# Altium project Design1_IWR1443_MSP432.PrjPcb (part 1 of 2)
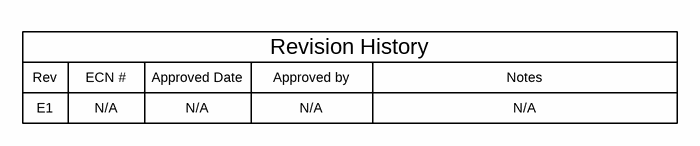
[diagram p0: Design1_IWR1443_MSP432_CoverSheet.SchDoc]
CopyrightYear: 2016; PCB_Layout: N/A; PCB_Rev: E1; PRJ_Customer: Public Release; PRJ_Engineer: Michelle Liu; PRJ_Title: Design1 with IR1443 and MSP432; SCH_Rev: E1; TechSupport: http://www.ti.com/support; TID: N/A
6 sheets, 236 parts. Net scope: global (net labels, ports and power ports of the same name join across sheets).
Sheets:
  Design1_IWR1443_MSP432_CoverSheet.SchDoc
  Design1_IWR1443_interfaces.SchDoc
  Design1_MSP432.SchDoc
  Design1_LowVoltage.SchDoc
  Design1_HighVoltage.SchDoc
  Design1_EVM_Hardware.SchDoc

## Sheet Design1_IWR1443_MSP432_CoverSheet.SchDoc: Block Diagram
size 431 x 279 mm; Date: Not shown in title block; ApprovedBy: Not shown in title block; CheckedBy: Not shown in title block; Author: Not shown in title block; CompanyName: Not shown in title block; DrawnBy: Michelle Liu; Engineer: Not shown in title block; Organization: Not shown in title block; Address1: Not shown in title block; Address2: Not shown in title block; Address3: Not shown in title block; Address4: Not shown in title block; DocumentNumber: 1; Revision: Use project parameter SCH_Rev; SheetNumber: 1; SheetTotal: 6; PageSetup: Record=PageOptions¦CenterHorizontal=True¦CenterVertical=True¦PrintScale=1.00¦XCorrection=1.00¦YCorrection=1.00¦PrintKind=0¦BorderSize=5000000¦LeftOffset=0¦BottomOffset=0¦Orientation=2¦PaperLength=1000¦PaperWidth=1000¦Scale=100¦PaperSource=15¦PrintQuality=600¦MediaType=1¦DitherType=10¦PaperKind=Letter¦PrintScaleMode=1

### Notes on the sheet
- Rev
- E1
- ECN #
- N/A
- Approved Date
- Approved by
- Revision History
- Notes

## Sheet Design1_IWR1443_interfaces.SchDoc: IWR1443
size 431 x 279 mm; Date: Not shown in title block; ApprovedBy: Not shown in title block; CheckedBy: Not shown in title block; Author: Not shown in title block; CompanyName: Not shown in title block; DrawnBy: Michelle Liu; Engineer: Not shown in title block; Organization: Not shown in title block; Address1: Not shown in title block; Address2: Not shown in title block; Address3: Not shown in title block; Address4: Not shown in title block; DocumentNumber: 2; Revision: Use project parameter SCH_Rev; SheetNumber: 2; SheetTotal: 6; PageSetup: Record=PageOptions¦CenterHorizontal=True¦CenterVertical=True¦PrintScale=1.00¦XCorrection=1.00¦YCorrection=1.00¦PrintKind=0¦BorderSize=5000000¦LeftOffset=0¦BottomOffset=0¦Orientation=2¦PaperLength=1000¦PaperWidth=1000¦Scale=100¦PaperSource=15¦PrintQuality=-3¦MediaType=1¦DitherType=10¦PrintScaleMode=1¦PaperKind=Letter¦PaperIndex=1
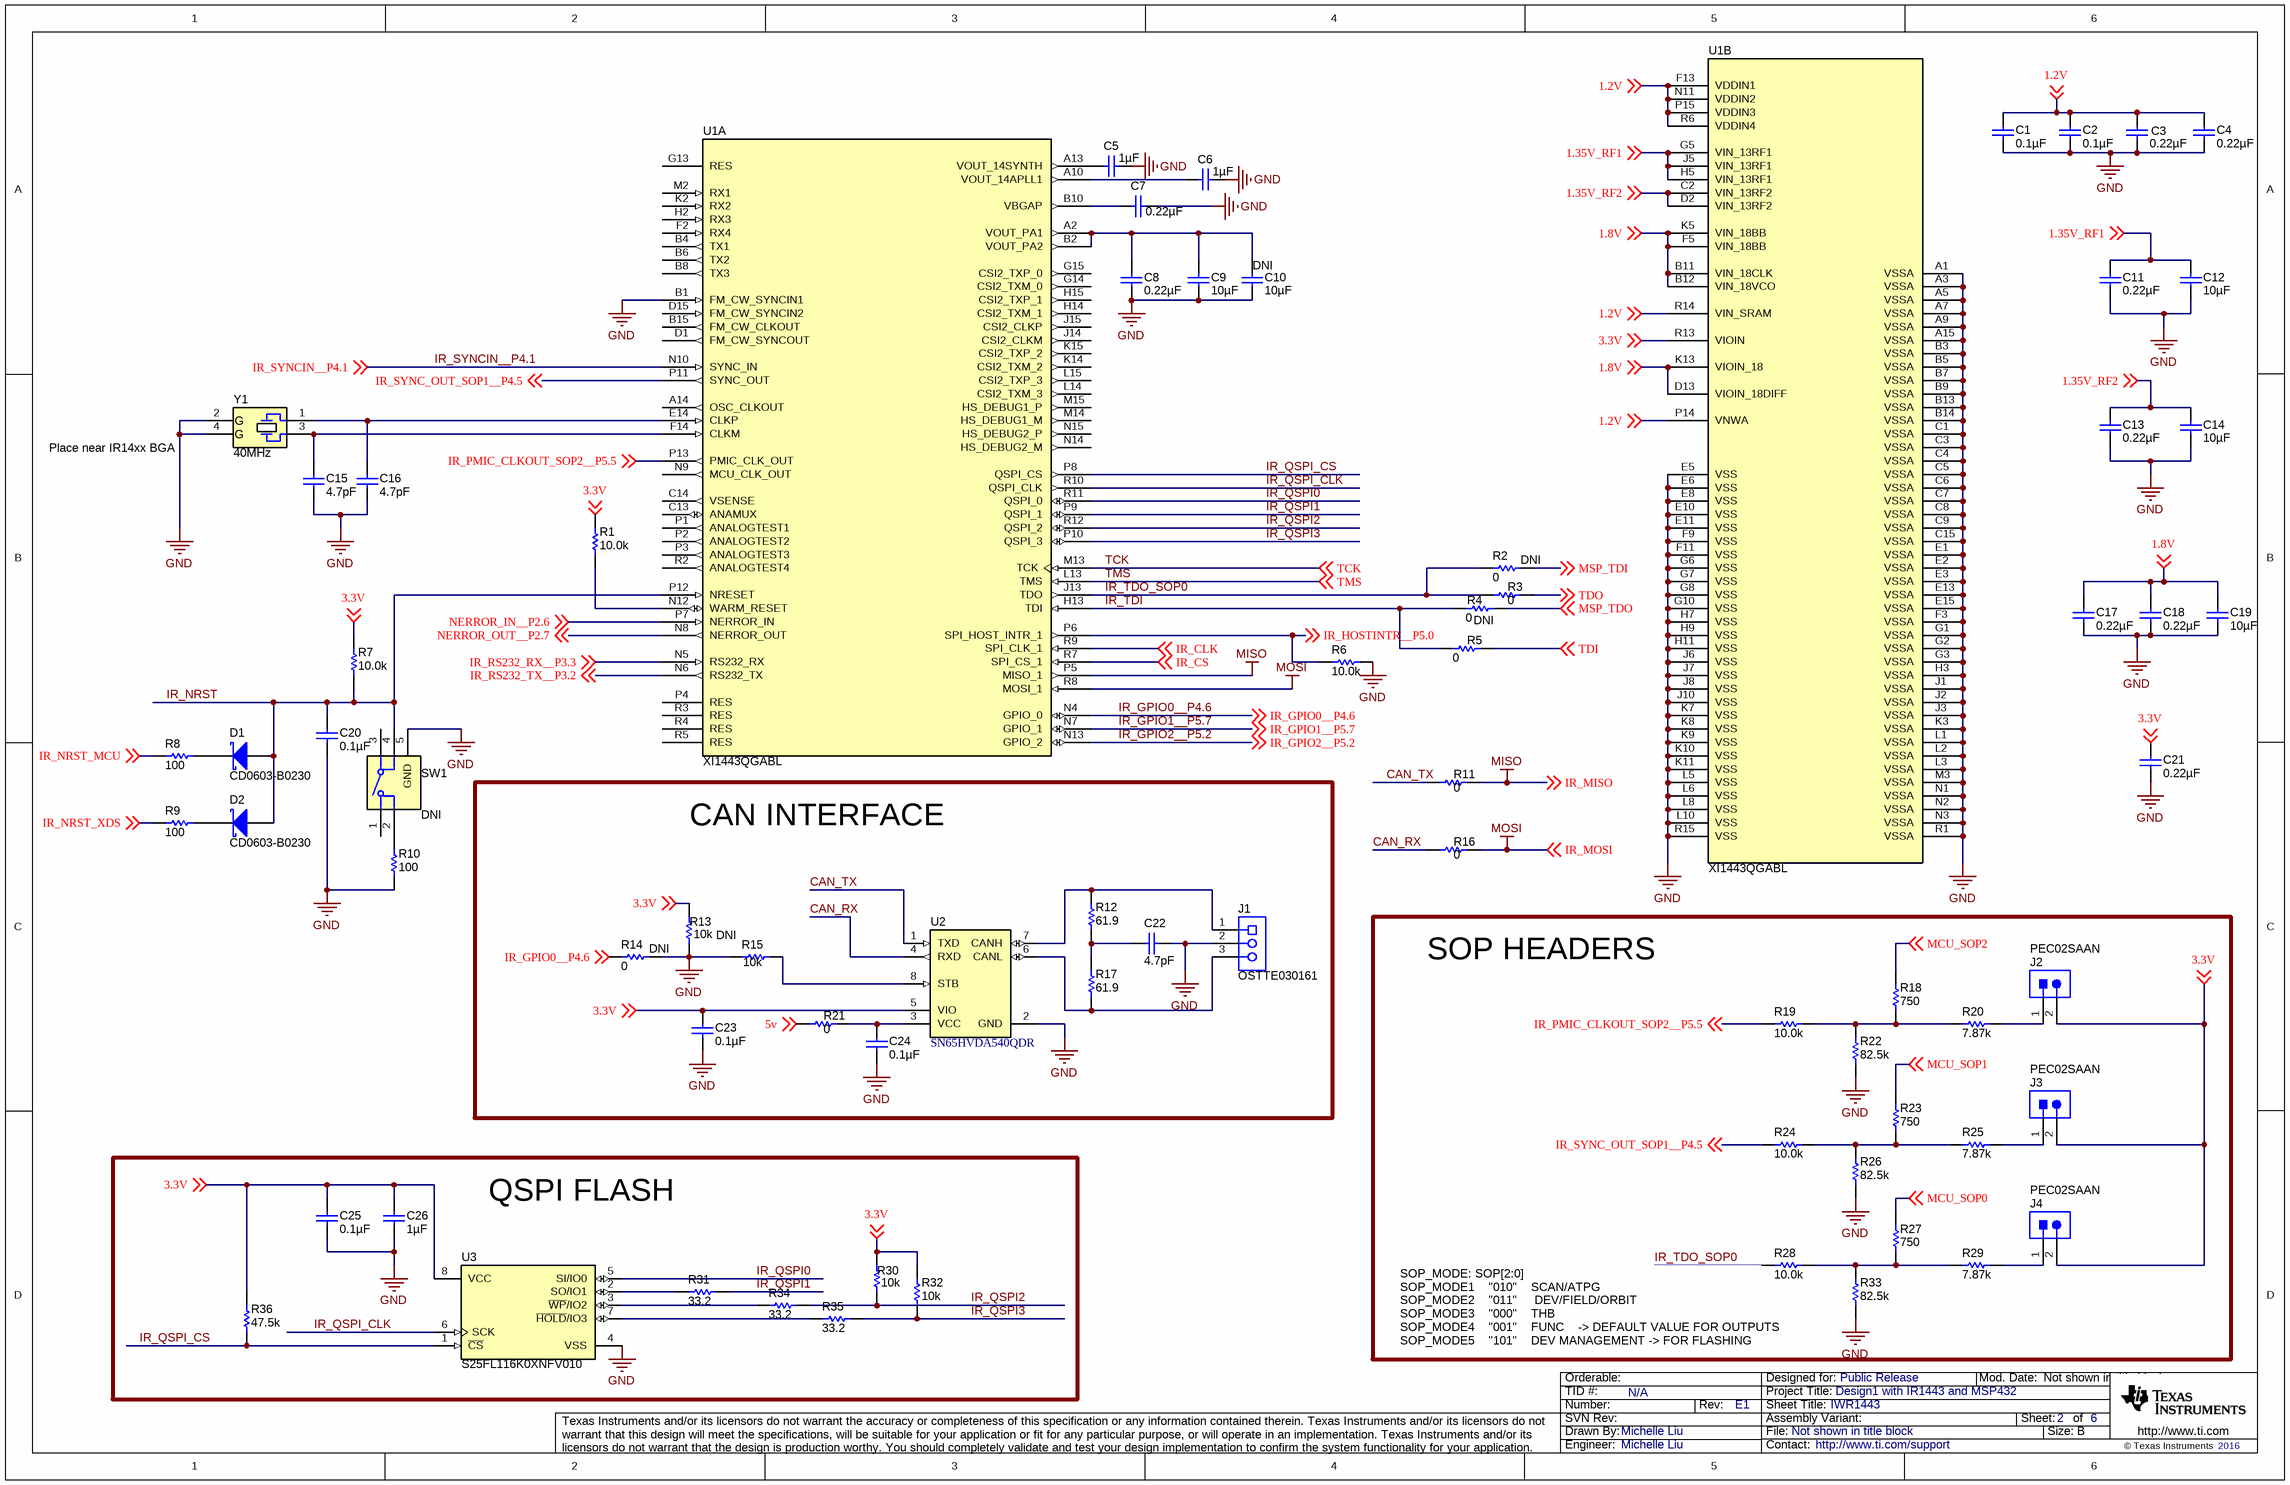
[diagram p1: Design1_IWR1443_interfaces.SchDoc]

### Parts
C1  ValueDisplayed: 0.1µF  [0402]  (hidden comment: GCM155R71C104KA55D)
C2  ValueDisplayed: 0.1µF  [0402]  (hidden comment: GCM155R71C104KA55D)
C3  ValueDisplayed: 0.22µF  [0603]  (hidden comment: GCM155R71C224KE02)
C4  ValueDisplayed: 0.22µF  [0603]  (hidden comment: GCM155R71C224KE02)
C5  ValueDisplayed: 1µF  [0603]  (hidden comment: GCM188R71C105KA64D)
C6  ValueDisplayed: 1µF  [0603]  (hidden comment: GCM188R71C105KA64D)
C7  ValueDisplayed: 0.22µF  [0603]  (hidden comment: GCM155R71C224KE02)
C8  ValueDisplayed: 0.22µF  [0603]  (hidden comment: GCM155R71C224KE02)
C9  ValueDisplayed: 10µF  [0805_HV]  (hidden comment: GCM21BR71A106KE22L)
C10  DNI  ValueDisplayed: 10µF  [0805_HV]
C11  ValueDisplayed: 0.22µF  [0603]  (hidden comment: GCM155R71C224KE02)
C12  ValueDisplayed: 10µF  [0805_HV]  (hidden comment: GCM21BR71A106KE22L)
C13  ValueDisplayed: 0.22µF  [0603]  (hidden comment: GCM155R71C224KE02)
C14  ValueDisplayed: 10µF  [0805_HV]  (hidden comment: GCM21BR71A106KE22L)
C15  ValueDisplayed: 4.7pF  [0402]  (hidden comment: GRM1555C1H4R7WA01D)
C16  ValueDisplayed: 4.7pF  [0402]  (hidden comment: GRM1555C1H4R7WA01D)
C17  ValueDisplayed: 0.22µF  [0603]  (hidden comment: GCM155R71C224KE02)
C18  ValueDisplayed: 0.22µF  [0603]  (hidden comment: GCM155R71C224KE02)
C19  ValueDisplayed: 10µF  [0805_HV]  (hidden comment: GCM21BR71A106KE22L)
C20  ValueDisplayed: 0.1µF  [0402]  (hidden comment: GCM155R71C104KA55D)
C21  ValueDisplayed: 0.22µF  [0603]  (hidden comment: GCM155R71C224KE02)
C22  ValueDisplayed: 4.7pF  [0402]  (hidden comment: GJM1555C1H4R7BB01D)
C23  ValueDisplayed: 0.1µF  [0402]  (hidden comment: CGA2B3X7R1H104K050BB)
C24  ValueDisplayed: 0.1µF  [0402]  (hidden comment: CGA2B3X7R1H104K050BB)
C25  ValueDisplayed: 0.1µF  [0402]  (hidden comment: C1005X5R1A104K050BA)
C26  ValueDisplayed: 1µF  [0402S]  (hidden comment: GRM155R6YA105ME11D)
D1  CD0603-B0230  [Diode_0603]
D2  CD0603-B0230  [Diode_0603]
J1  OSTTE030161  [On-Shore_OSTTE030161]
J2  PEC02SAAN  [CONN_PEC02SAAN]
J3  PEC02SAAN  [CONN_PEC02SAAN]
J4  PEC02SAAN  [CONN_PEC02SAAN]
R1  ValueDisplayed: 10.0k  [0402]  (hidden comment: CRCW040210K0FKED)
R2  DNI  ValueDisplayed: 0  [0402]
R3  ValueDisplayed: 0  [0402]  (hidden comment: RC0402JR-070RL)
R4  DNI  ValueDisplayed: 0  [0402]
R5  ValueDisplayed: 0  [0402]  (hidden comment: RC0402JR-070RL)
R6  ValueDisplayed: 10.0k  [0402]  (hidden comment: CRCW040210K0FKED)
R7  ValueDisplayed: 10.0k  [0402]  (hidden comment: CRCW040210K0FKED)
R8  ValueDisplayed: 100  [0402]  (hidden comment: ERJ-2GEJ101X)
R9  ValueDisplayed: 100  [0402]  (hidden comment: ERJ-2GEJ101X)
R10  ValueDisplayed: 100  [0402]  (hidden comment: ERJ-2GEJ101X)
R11  ValueDisplayed: 0  [0402]  (hidden comment: RC0402JR-070RL)
R12  ValueDisplayed: 61.9  [0402]  (hidden comment: CRCW040261R9FKED)
R13  DNI  ValueDisplayed: 10k  [0402]
R14  DNI  ValueDisplayed: 0  [0402]
R15  ValueDisplayed: 10k  [0402]  (hidden comment: CRCW040210K0JNED)
R16  ValueDisplayed: 0  [0402]  (hidden comment: RC0402JR-070RL)
R17  ValueDisplayed: 61.9  [0402]  (hidden comment: CRCW040261R9FKED)
R18  ValueDisplayed: 750  [0402]  (hidden comment: CRCW0402750RFKED)
R19  ValueDisplayed: 10.0k  [0402]  (hidden comment: CRCW040210K0FKED)
R20  ValueDisplayed: 7.87k  [0402]  (hidden comment: CRCW04027K87FKED)
R21  ValueDisplayed: 0  [0402]  (hidden comment: RC0402JR-070RL)
R22  ValueDisplayed: 82.5k  [0402]  (hidden comment: CRCW040282K5FKED)
R23  ValueDisplayed: 750  [0402]  (hidden comment: CRCW0402750RFKED)
R24  ValueDisplayed: 10.0k  [0402]  (hidden comment: CRCW040210K0FKED)
R25  ValueDisplayed: 7.87k  [0402]  (hidden comment: CRCW04027K87FKED)
R26  ValueDisplayed: 82.5k  [0402]  (hidden comment: CRCW040282K5FKED)
R27  ValueDisplayed: 750  [0402]  (hidden comment: CRCW0402750RFKED)
R28  ValueDisplayed: 10.0k  [0402]  (hidden comment: CRCW040210K0FKED)
R29  ValueDisplayed: 7.87k  [0402]  (hidden comment: CRCW04027K87FKED)
R30  ValueDisplayed: 10k  [0402]  (hidden comment: CRCW040210K0JNED)
R31  ValueDisplayed: 33.2  [0201]  (hidden comment: CRCW020133R2FNED)
R32  ValueDisplayed: 10k  [0402]  (hidden comment: CRCW040210K0JNED)
R33  ValueDisplayed: 82.5k  [0402]  (hidden comment: CRCW040282K5FKED)
R34  ValueDisplayed: 33.2  [0201]  (hidden comment: CRCW020133R2FNED)
R35  ValueDisplayed: 33.2  [0201]  (hidden comment: CRCW020133R2FNED)
R36  ValueDisplayed: 47.5k  [0402]  (hidden comment: CRCW040247K5FKED)
SW1  DNI  [SW_KMR243GLFG]
U1  XI1443QGABL  [ABL0161A]  (parts A,B of 2)
U2  SN65HVDA540QDR  [D0008A_N]
U3  S25FL116K0XNFV010  [WND008]
Y1  Frequency: 40MHz  [Kyocera_CX3225SA]  (hidden comment: CX3225SA40000D0PTWCC)

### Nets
1.2V: C1.1 C2.1 C3.1 C4.1 U1.F13(VDDIN1) U1.N11(VDDIN2) U1.P14(VNWA) U1.P15(VDDIN3) U1.R6(VDDIN4) U1.R14(VIN_SRAM) ; off-sheet 1.2V
1.8V: C17.1 C18.1 C19.1 U1.B11(VIN_18CLK) U1.B12(VIN_18VCO) U1.D13(VIOIN_18DIFF) U1.F5(VIN_18BB) U1.K5(VIN_18BB) U1.K13(VIOIN_18) ; off-sheet 1.8V
1.35V_RF1: C11.1 C12.1 U1.G5(VIN_13RF1) U1.H5(VIN_13RF1) U1.J5(VIN_13RF1) ; off-sheet 1.35V_RF1
1.35V_RF2: C13.1 C14.1 U1.C2(VIN_13RF2) U1.D2(VIN_13RF2) ; off-sheet 1.35V_RF2
3.3V: C21.1 C23.1 C25.1 C26.1 J2.2 J3.2 J4.2 R1.2 R7.2 R13.2 R30.2 R32.2 R36.2 U1.R13(VIOIN) U2.5(VIO) U3.8(VCC) ; off-sheet 3.3V
5v: R21.1 ; off-sheet 5v
GND: C1.2 C2.2 C3.2 C4.2 C5.1 C6.1 C7.1 C8.2 C9.2 C10.2 C11.2 C12.2 C13.2 C14.2 C15.2 C16.2 C17.2 C18.2 C19.2 C20.2 C21.2 C22.1 C23.2 C24.2 C25.2 C26.2 J1.2 R6.1 R10.1 R13.1 R14.2 R15.2 R22.1 R26.1 R33.1 SW1.5(GND) U1.A1(VSSA) U1.A3(VSSA) U1.A5(VSSA) U1.A7(VSSA) U1.A9(VSSA) U1.A15(VSSA) U1.B1(FM_CW_SYNCIN1) U1.B3(VSSA) U1.B5(VSSA) U1.B7(VSSA) U1.B9(VSSA) U1.B13(VSSA) U1.B14(VSSA) U1.C1(VSSA) U1.C3(VSSA) U1.C4(VSSA) U1.C5(VSSA) U1.C6(VSSA) U1.C7(VSSA) U1.C8(VSSA) U1.C9(VSSA) U1.C15(VSSA) U1.E1(VSSA) U1.E2(VSSA) U1.E3(VSSA) U1.E5(VSS) U1.E6(VSS) U1.E8(VSS) U1.E10(VSS) U1.E11(VSS) U1.E13(VSSA) U1.E15(VSSA) U1.F3(VSSA) U1.F9(VSS) U1.F11(VSS) U1.G1(VSSA) U1.G2(VSSA) U1.G3(VSSA) U1.G6(VSS) U1.G7(VSS) U1.G8(VSS) U1.G10(VSS) U1.H3(VSSA) U1.H7(VSS) U1.H9(VSS) U1.H11(VSS) U1.J1(VSSA) U1.J2(VSSA) U1.J3(VSSA) U1.J6(VSS) U1.J7(VSS) U1.J8(VSS) U1.J10(VSS) U1.K3(VSSA) U1.K7(VSS) U1.K8(VSS) U1.K9(VSS) U1.K10(VSS) U1.K11(VSS) U1.L1(VSSA) U1.L2(VSSA) U1.L3(VSSA) U1.L5(VSS) U1.L6(VSS) U1.L8(VSS) U1.L10(VSS) U1.M3(VSSA) U1.N1(VSSA) U1.N2(VSSA) U1.N3(VSSA) U1.R1(VSSA) U1.R15(VSS) U2.2(GND) U3.4(VSS) Y1.2(GND) Y1.4(GND)
MISO: R11.2 U1.P5(MISO_1) ; off-sheet IR_MISO  [also labelled IR_MISO]
MOSI: R16.2 U1.R8(MOSI_1) ; off-sheet IR_MOSI  [also labelled IR_MOSI]
CAN_RX: R16.1 U2.4(RXD)
CAN_TX: R11.1 U2.1(TXD)
IR_CLK: U1.R9(SPI_CLK_1) ; off-sheet IR_CLK
IR_CS: U1.R7(SPI_CS_1) ; off-sheet IR_CS
IR_GPIO0__P4.6: R14.1 U1.N4(GPIO_0) ; off-sheet IR_GPIO0__P4.6
IR_GPIO1__P5.7: U1.N7(GPIO_1) ; off-sheet IR_GPIO1__P5.7
IR_GPIO2__P5.2: U1.N13(GPIO_2) ; off-sheet IR_GPIO2__P5.2
IR_HOSTINTR__P5.0: R6.2 U1.P6(SPI_HOST_INTR_1) ; off-sheet IR_HOSTINTR__P5.0
IR_NRST: C20.1 D1.2(A) D2.2(A) R7.1 SW1.4 U1.P12(NRESET)
IR_NRST_MCU: R8.1 ; off-sheet IR_NRST_MCU
IR_NRST_XDS: R9.1 ; off-sheet IR_NRST_XDS
IR_PMIC_CLKOUT_SOP2__P5.5: R19.2 U1.P13(PMIC_CLK_OUT) ; off-sheet IR_PMIC_CLKOUT_SOP2__P5.5
IR_QSPI0: U1.R11(QSPI_0) U3.5(SI/IO0)
IR_QSPI1: R31.2 U1.P9(QSPI_1)
IR_QSPI2: R30.1 R34.2 U1.R12(QSPI_2)
IR_QSPI3: R32.1 R35.2 U1.P10(QSPI_3)
IR_QSPI_CLK: U1.R10(QSPI_CLK) U3.6(SCK)
IR_QSPI_CS: R36.1 U1.P8(QSPI_CS) U3.1(~{CS})
IR_RS232_RX__P3.3: U1.N5(RS232_RX) ; off-sheet IR_RS232_RX__P3.3
IR_RS232_TX__P3.2: U1.N6(RS232_TX) ; off-sheet IR_RS232_TX__P3.2
IR_SYNC_OUT_SOP1__P4.5: R24.2 U1.P11(SYNC_OUT) ; off-sheet IR_SYNC_OUT_SOP1__P4.5
IR_SYNCIN__P4.1: U1.N10(SYNC_IN) ; off-sheet IR_SYNCIN__P4.1
IR_TDI: R4.1 R5.1 U1.H13(TDI)
IR_TDO_SOP0: R2.1 R3.1 R28.2 U1.J13(TDO)
MCU_SOP0: R27.2 ; off-sheet MCU_SOP0
MCU_SOP1: R23.2 ; off-sheet MCU_SOP1
MCU_SOP2: R18.2 ; off-sheet MCU_SOP2
MSP_TDI: R2.2 ; off-sheet MSP_TDI
MSP_TDO: R4.2 ; off-sheet MSP_TDO
NERROR_IN__P2.6: U1.P7(NERROR_IN) ; off-sheet NERROR_IN__P2.6
NERROR_OUT__P2.7: U1.N8(NERROR_OUT) ; off-sheet NERROR_OUT__P2.7
TCK: U1.M13(TCK) ; off-sheet TCK
TDI: R5.2 ; off-sheet TDI
TDO: R3.2 ; off-sheet TDO
TMS: U1.L13(TMS) ; off-sheet TMS
NetC5_2: C5.2 U1.A13(VOUT_14SYNTH)
NetC6_2: C6.2 U1.A10(VOUT_14APLL1)
NetC7_2: C7.2 U1.B10(VBGAP)
NetC8_1: C8.1 C9.1 C10.1 U1.A2(VOUT_PA1) U1.B2(VOUT_PA2)
NetC15_1: C15.1 U1.F14(CLKM) Y1.3
NetC16_1: C16.1 U1.E14(CLKP) Y1.1
NetC22_2: C22.2 R12.1 R17.2
NetC24_1: C24.1 R21.2 U2.3(VCC)
NetD1_1: D1.1(K) R8.2
NetD2_1: D2.1(K) R9.2
NetJ1_1: J1.1 R12.2 U2.7(CANH)
NetJ1_3: J1.3 R17.1 U2.6(CANL)
NetJ2_1: J2.1 R20.2
NetJ3_1: J3.1 R25.2
NetJ4_1: J4.1 R29.2
NetR1_1: R1.1 U1.N12(WARM_RESET)
NetR10_2: R10.2 SW1.2
NetR15_1: R15.1 U2.8(STB)
NetR18_1: R18.1 R19.1 R20.1 R22.2
NetR23_1: R23.1 R24.1 R25.1 R26.2
NetR27_1: R27.1 R28.1 R29.1 R33.2
NetR31_1: R31.1 U3.2(SO/IO1)
NetR34_1: R34.1 U3.3(~{WP}/IO2)
NetR35_1: R35.1 U3.7(~{HOLD}/IO3)

Not connected (* = marked no-connect by the designer): SW1 1 3; U1 A14(OSC_CLKOUT) B4(TX1) B6(TX2) B8(TX3) B15(FM_CW_CLKOUT) C13(ANAMUX) C14(VSENSE) D1(FM_CW_SYNCOUT) D15(FM_CW_SYNCIN2) F2(RX4) G13(RES) G14(CSI2_TXM_0) G15(CSI2_TXP_0) H2(RX3) H14(CSI2_TXM_1) H15(CSI2_TXP_1) J14(CSI2_CLKM) J15(CSI2_CLKP) K2(RX2) K14(CSI2_TXM_2) K15(CSI2_TXP_2) L14(CSI2_TXM_3) L15(CSI2_TXP_3) M2(RX1) M14(HS_DEBUG1_M) M15(HS_DEBUG1_P) N9(MCU_CLK_OUT) N14(HS_DEBUG2_M) N15(HS_DEBUG2_P) P1(ANALOGTEST1) P2(ANALOGTEST2) P3(ANALOGTEST3) P4(RES) R2(ANALOGTEST4) R3(RES) R4(RES) R5(RES)

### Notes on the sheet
- IWR1443
- Place near IR14xx BGA
- CAN INTERFACE
- SOP HEADERS
- QSPI FLASH
- (near R28) SOP_MODE: SOP[2:0]
  SOP_MODE1    "010"    SCAN/ATPG
  SOP_MODE2    "011"     DEV/FIELD/ORBIT
  SOP_MODE3    "000"    THB
  SOP_MODE4    "001"    FUNC    -> DEFAULT VALUE FOR OUTPUTS
  SOP_MODE5    "101"    DEV MANAGEMENT -> FOR FLASHING

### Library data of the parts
C1 C2 C20 = GCM155R71C104KA55D: CAP, CERM, 0.1 µF, 16 V, +/- 10%, X7R, 0402; Manufacturer: MuRata; Polarized: N; CompType: Capacitor; Value: 0.1uF; U/M: EA; Cap_F: 0.0000001; Tolerance_%: 10; Value1: Unknown; VDC_V: 16; Value2: 16V; TaMin_C: -55; TaMax_C: 125; SizeArea_mm2: 0.5; SizeAreaWB_mm2: 3; SizeX_mm: 1; SizeZ_mm: 0.6; AEC Category: Q200
C3 C4 C7 C8 C11 C13 C17 C18 C21 = GCM155R71C224KE02: CAP, CERM, 0.22 µF, 16 V, +/- 10%, X7R, AEC-Q200 Grade 1, 0603; Manufacturer: MuRata; Polarized: N; CompType: Capacitor; Value: 0.22uF; U/M: EA; Cap_F: 0.00000022; Tolerance_%: 10; Value1: Unknown; VDC_V: 16; Value2: 16V; TaMin_C: -55; TaMax_C: 125; SizeArea_mm2: 1.28; SizeAreaWB_mm2: 4.68; SizeX_mm: 1.6; SizeY_mm: 0.8; SizeZ_mm: 1; AEC Category: Q200; AEC Qualified: Y
C5 C6 = GCM188R71C105KA64D: CAP, CERM, 1 µF, 16 V, +/- 10%, X7R, AEC-Q200 Grade 1, 0603; Manufacturer: MuRata; Polarized: N; CompType: Capacitor; Value: 1uF; U/M: EA; Cap_F: 0.000001; Tolerance_%: 10; Value1: Unknown; VDC_V: 16; Value2: 16V; TaMin_C: -55; TaMax_C: 125; SizeArea_mm2: 1.28; SizeAreaWB_mm2: 4.68; SizeX_mm: 1.6; SizeY_mm: 0.8; SizeZ_mm: 1; AEC Category: Q200; AEC Qualified: Y
C9 C10 C12 C14 C19 = GCM21BR71A106KE22L: CAP, CERM, 10 µF, 10 V, +/- 10%, X7R, 0805; Manufacturer: MuRata; Polarized: N; CompType: Capacitor; Value: 10uF; U/M: EA; Cap_F: 0.00001; Tolerance_%: 10; Value1: Unknown; Value2: 10V; TaMin_C: -55; TaMax_C: 125; Cap_Case: 0805; SizeArea_mm2: 2.5; SizeAreaWB_mm2: 6.75; SizeX_mm: 2; SizeY_mm: 1.25; SizeZ_mm: 1.45; AEC Category: Q200
C15 C16 = GRM1555C1H4R7WA01D: CAP, CERM, 4.7 pF, 50 V, +/- 1%, C0G/NP0, 0402; Manufacturer: MuRata; Polarized: N; CompType: Capacitor; Value: 4.7pF; U/M: EA; Cap_F: 0.0000000000047; Tolerance_%: 1; Value1: Unknown; VDC_V: 50; Value2: 50V; TaMin_C: -55; TaMax_C: 125; SizeArea_mm2: 0.5; SizeAreaWB_mm2: 3; SizeZ_mm: 0.6; AEC Category: Q200
C22 = GJM1555C1H4R7BB01D: CAP, CERM, 4.7 pF, 50 V, +/- 2%, C0G/NP0, 0402; Manufacturer: MuRata; Polarized: N; CompType: Capacitor; Value: 4.7pF; U/M: EA; Cap_F: 0.0000000000047; Tolerance_%: 2; Value1: Unknown; VDC_V: 50; Value2: 50V; TaMin_C: -55; TaMax_C: 125; SizeArea_mm2: 0.5; SizeAreaWB_mm2: 3; SizeX_mm: 1; SizeZ_mm: 0.6; AEC Category: Q200
C23 C24 = CGA2B3X7R1H104K050BB: CAP, CERM, 0.1 µF, 50 V, +/- 10%, X7R, AEC-Q200 Grade 1, 0402; Manufacturer: TDK; Polarized: N; CompType: Capacitor; Value: 0.1uF; U/M: EA; Cap_F: 0.0000001; Tolerance_%: 10; ESR_ohm: 0.039064; Value1: 0.039064 ohm; VDC_V: 50; Value2: 50V; IRMS_A: 0.814669; TaMin_C: -55; TaMax_C: 125; SizeArea_mm2: 0.5; SizeAreaWB_mm2: 3; SizeX_mm: 1; SizeZ_mm: 0.6; AEC Category: Q200; AEC Qualified: Y
C25 = C1005X5R1A104K050BA: CAP, CERM, 0.1 µF, 10 V, +/- 10%, X5R, 0402; Manufacturer: TDK; Polarized: N; CompType: Capacitor; Value: 0.1uF; U/M: EA; Cap_F: 0.0000001; Tolerance_%: 10; Value1: Unknown; Value2: 10V; TaMin_C: -55; TaMax_C: 85; SizeArea_mm2: 0.5; SizeAreaWB_mm2: 3; SizeX_mm: 1; SizeZ_mm: 0.6; AEC Category: Q200
C26 = GRM155R6YA105ME11D: CAP, CERM, 1 µF, 35 V, +/- 20%, X5R, 0402; Manufacturer: MuRata; Polarized: N; CompType: Capacitor; Value: 1uF; U/M: EA; Cap_F: 0.000001; Tolerance_%: 20; Value1: Unknown; VDC_V: 35; Value2: 35V; TaMin_C: -55; TaMax_C: 85; Cap_Case: 0402; SizeArea_mm2: 0.5; SizeAreaWB_mm2: 3; SizeX_mm: 1; SizeZ_mm: 0.6; AEC Category: Q200
D1 D2 = CD0603-B0230: Diode, Schottky, 35 V, 0.2 A, 0603 Diode; Manufacturer: Bourns; U/M: EA; Vf_V: 0.5; Value: 35V; Value1: 0.2A; Value2: 0.5V; Io_A: 0.2; Vr_V: 35; TJmax_C: 125; SizeAreaWB_mm2: 5.13; SizeArea_mm2: 1.53; SizeX_mm: 1.7; SizeY_mm: 0.9; SizeZ_mm: 0.75; AEC Category: Q101
J1 = OSTTE030161: Terminal Block, 3.5mm, 3x1, Tin, R/A, TH; Manufacturer: On-Shore Technology; SymbolCreator: a0412235; Pitch_mm: 3.5; Gender: Female; Row_Count: 1; Current_A: 10; Voltage_V: 125; Cert_CSA: Y
J2-J4 = PEC02SAAN: Header, 100mil, 2x1, Tin, TH; Manufacturer: Sullins Connector Solutions; SymbolCreator: a0412235; Pitch_mm: 2.54; Gender: Male; Shrouded: N; Row_Count: 1; Current_A: 3; Voltage_V: 1800; Cert_UL: Y
R1 R6 R7 R19 R24 R28 = CRCW040210K0FKED: RES, 10.0 k, 1%, 0.063 W, 0402; Manufacturer: Vishay-Dale; CompType: Resistor; Value: 10.0k; Res_ohm: 10000; Value_Code: 10k0; Tolerance_%: 1; Power_W: 0.063; Value2: 0.063W; VDC_V: 50; TempCo: 100 ppm/C; SizeArea_mm2: 0.5; SizeZ_mm: 0.6; EIA_Code: E96; U/M: EA; AEC Category: Q200
R2-R5 R11 R14 R16 R21 = RC0402JR-070RL: RES, 0, 5%, 0.063 W, 0402; Manufacturer: Yageo America; CompType: Resistor; Value: 0; Value_Code: 0000; Tolerance_%: 5; Power_W: 0.063; Value2: 0.063W; VDC_V: 50; TempCo: 200 ppm/C; SizeArea_mm2: 0.5; SizeX_mm: 1; SizeZ_mm: 0.6; EIA_Code: E24; U/M: EA; AEC Category: Q200
R8-R10 = ERJ-2GEJ101X: RES, 100, 5%, 0.1 W, AEC-Q200 Grade 0, 0402; Manufacturer: Panasonic; CompType: Resistor; Value: 100; Value_Code: 100R; Tolerance_%: 5; Power_W: 0.1; Value2: 0.1W; TempCo: 200 ppm/C; SizeArea_mm2: 0.5; SizeX_mm: 1; SizeZ_mm: 0.6; EIA_Code: E24; U/M: EA; AEC Category: Q200; AEC Qualified: Y; AEC Grade: 0
R12 R17 = CRCW040261R9FKED: RES, 61.9, 1%, 0.063 W, 0402; Manufacturer: Vishay-Dale; CompType: Resistor; Value: 61.9; Value_Code: 61R9; Tolerance_%: 1; Power_W: 0.063; Value2: 0.063W; VDC_V: 50; TempCo: 100 ppm/C; SizeArea_mm2: 0.5; SizeZ_mm: 0.6; EIA_Code: E96; U/M: EA; AEC Category: Q200
R13 R15 R30 R32 = CRCW040210K0JNED: RES, 10 k, 5%, 0.063 W, 0402; Manufacturer: Vishay-Dale; CompType: Resistor; Value: 10k; Res_ohm: 10000; Value_Code: 10k0; Tolerance_%: 5; Power_W: 0.063; Value2: 0.063W; VDC_V: 50; TempCo: 200 ppm/C; SizeArea_mm2: 0.5; SizeX_mm: 1; SizeZ_mm: 0.6; EIA_Code: E24; U/M: EA; AEC Category: Q200
R18 R23 R27 = CRCW0402750RFKED: RES, 750, 1%, 0.063 W, AEC-Q200 Grade 0, 0402; Manufacturer: Vishay-Dale; CompType: Resistor; Value: 750; Value_Code: 750R; Tolerance_%: 1; Power_W: 0.063; Value2: 0.063W; VDC_V: 50; TempCo: 100 ppm/C; SizeArea_mm2: 0.5; SizeZ_mm: 0.6; EIA_Code: E96; U/M: EA; AEC Category: Q200; AEC Qualified: Y; AEC Grade: 0
R20 R25 R29 = CRCW04027K87FKED: RES, 7.87 k, 1%, 0.063 W, AEC-Q200 Grade 0, 0402; Manufacturer: Vishay-Dale; CompType: Resistor; Value: 7.87k; Res_ohm: 7870; Value_Code: 7k87; Tolerance_%: 1; Power_W: 0.063; Value2: 0.063W; VDC_V: 50; TempCo: 100 ppm/C; SizeArea_mm2: 0.5; SizeZ_mm: 0.6; EIA_Code: E96; U/M: EA; AEC Category: Q200; AEC Qualified: Y; AEC Grade: 0
R22 R26 R33 = CRCW040282K5FKED: RES, 82.5 k, 1%, 0.063 W, AEC-Q200 Grade 0, 0402; Manufacturer: Vishay-Dale; CompType: Resistor; Value: 82.5k; Res_ohm: 82500; Value_Code: 82k5; Tolerance_%: 1; Power_W: 0.063; Value2: 0.063W; VDC_V: 50; TempCo: 100 ppm/C; SizeArea_mm2: 0.5; SizeZ_mm: 0.6; EIA_Code: E96; U/M: EA; AEC Category: Q200; AEC Qualified: Y; AEC Grade: 0
R31 R34 R35 = CRCW020133R2FNED: RES, 33.2, 1%, 0.05 W, 0201; Manufacturer: Vishay-Dale; CompType: Resistor; Value: 33.2; Value_Code: 33R2; Tolerance_%: 1; Power_W: 0.05; Value2: 0.05W; TempCo: 200 ppm/C; SizeArea_mm2: 0.18; SizeX_mm: 0.6; SizeY_mm: 0.3; SizeZ_mm: 0.26; EIA_Code: E96; U/M: EA; AEC Category: Q200; AEC Qualified: N
R36 = CRCW040247K5FKED: RES, 47.5 k, 1%, 0.063 W, 0402; Manufacturer: Vishay-Dale; CompType: Resistor; Value: 47.5k; Res_ohm: 47500; Value_Code: 47k5; Tolerance_%: 1; Power_W: 0.063; Value2: 0.063W; VDC_V: 50; TempCo: 100 ppm/C; SizeArea_mm2: 0.5; SizeZ_mm: 0.6; EIA_Code: E96; U/M: EA; AEC Category: Q200
SW1 = KMR243GLFG: Switch, SPST-NO, Off-Mom, 0.01 A, 32 VDC, SMD; Manufacturer: C&K Components; SymbolCreator: Altium; SizeAreaWB_mm2: 21.28; SizeArea_mm2: 12.88; SizeX_mm: 4.6; SizeY_mm: 2.8; SizeZ_mm: 1.9; VDC_V: 32; PositionCount: 1; CurrentRating_mA: 10
U1 = XI1443QGABL: Single Chip 77 and 79 GHz FMCW Transceiver, ABL0161A (FCBGA-161); Manufacturer: Texas Instruments; SymbolCreator: Altium; SizeArea_mm2: 108.16; SizeAreaWB_mm2: 153.76; SizeX_mm: 10.4; SizeZ_mm: 1.17; CompType: IC; U/M: EA
U2 = SN65HVDA540QDR: 5 V CAN Transceiver with I/O Level Shifting and Supply Optimization, 70 mA, 4.75 to 5.25 V, -40 to 125 degC, 8-pin SOIC (D), Green (RoHS & no Sb/Br); Manufacturer: Texas Instruments; Alternate PartNumber: Equivalent; Drivers Per Package: 1; Bus Fault Voltage(V): -27 to 40; Low Power Mode: Yes; ICC(Max)(mA): 70; Rating: Catalog
U3 = S25FL116K0XNFV010: 16 Mbit (2 Mbyte), 3.0 V SPI Flash Memory, WND008; Manufacturer: Cypress Semiconductor; SymbolCreator: Altium; SizeAreaWB_mm2: 56; SizeArea_mm2: 30; SizeX_mm: 6; SizeY_mm: 5; SizeZ_mm: 0.8
Y1 = CX3225SA40000D0PTWCC: Crystal, 40 MHz, 8pF, SMD; Manufacturer: Kyocera; SymbolCreator: a0411947; SizeAreaWB_mm2: 14.7; SizeArea_mm2: 8; SizeX_mm: 2.5; SizeY_mm: 3.2; SizeZ_mm: 0.8; U/M: EA; TaMin_C: -40; TaMax_C: 125; Frequency Stability: ±200ppm

## Sheet Design1_MSP432.SchDoc: MSP432P401R
size 431 x 279 mm; Date: Not shown in title block; ApprovedBy: Not shown in title block; CheckedBy: Not shown in title block; Author: Not shown in title block; CompanyName: Not shown in title block; DrawnBy: Michelle Liu; Engineer: Not shown in title block; Organization: Not shown in title block; Address1: Not shown in title block; Address2: Not shown in title block; Address3: Not shown in title block; Address4: Not shown in title block; DocumentNumber: 3; Revision: Use project parameter SCH_Rev; SheetNumber: 3; SheetTotal: 6; PageSetup: Record=PageOptions¦CenterHorizontal=True¦CenterVertical=True¦PrintScale=1.00¦XCorrection=1.00¦YCorrection=1.00¦PrintKind=0¦BorderSize=5000000¦LeftOffset=0¦BottomOffset=0¦Orientation=2¦PaperLength=1000¦PaperWidth=1000¦Scale=100¦PaperSource=15¦PrintQuality=600¦MediaType=1¦DitherType=10¦PaperKind=Letter¦PrintScaleMode=1
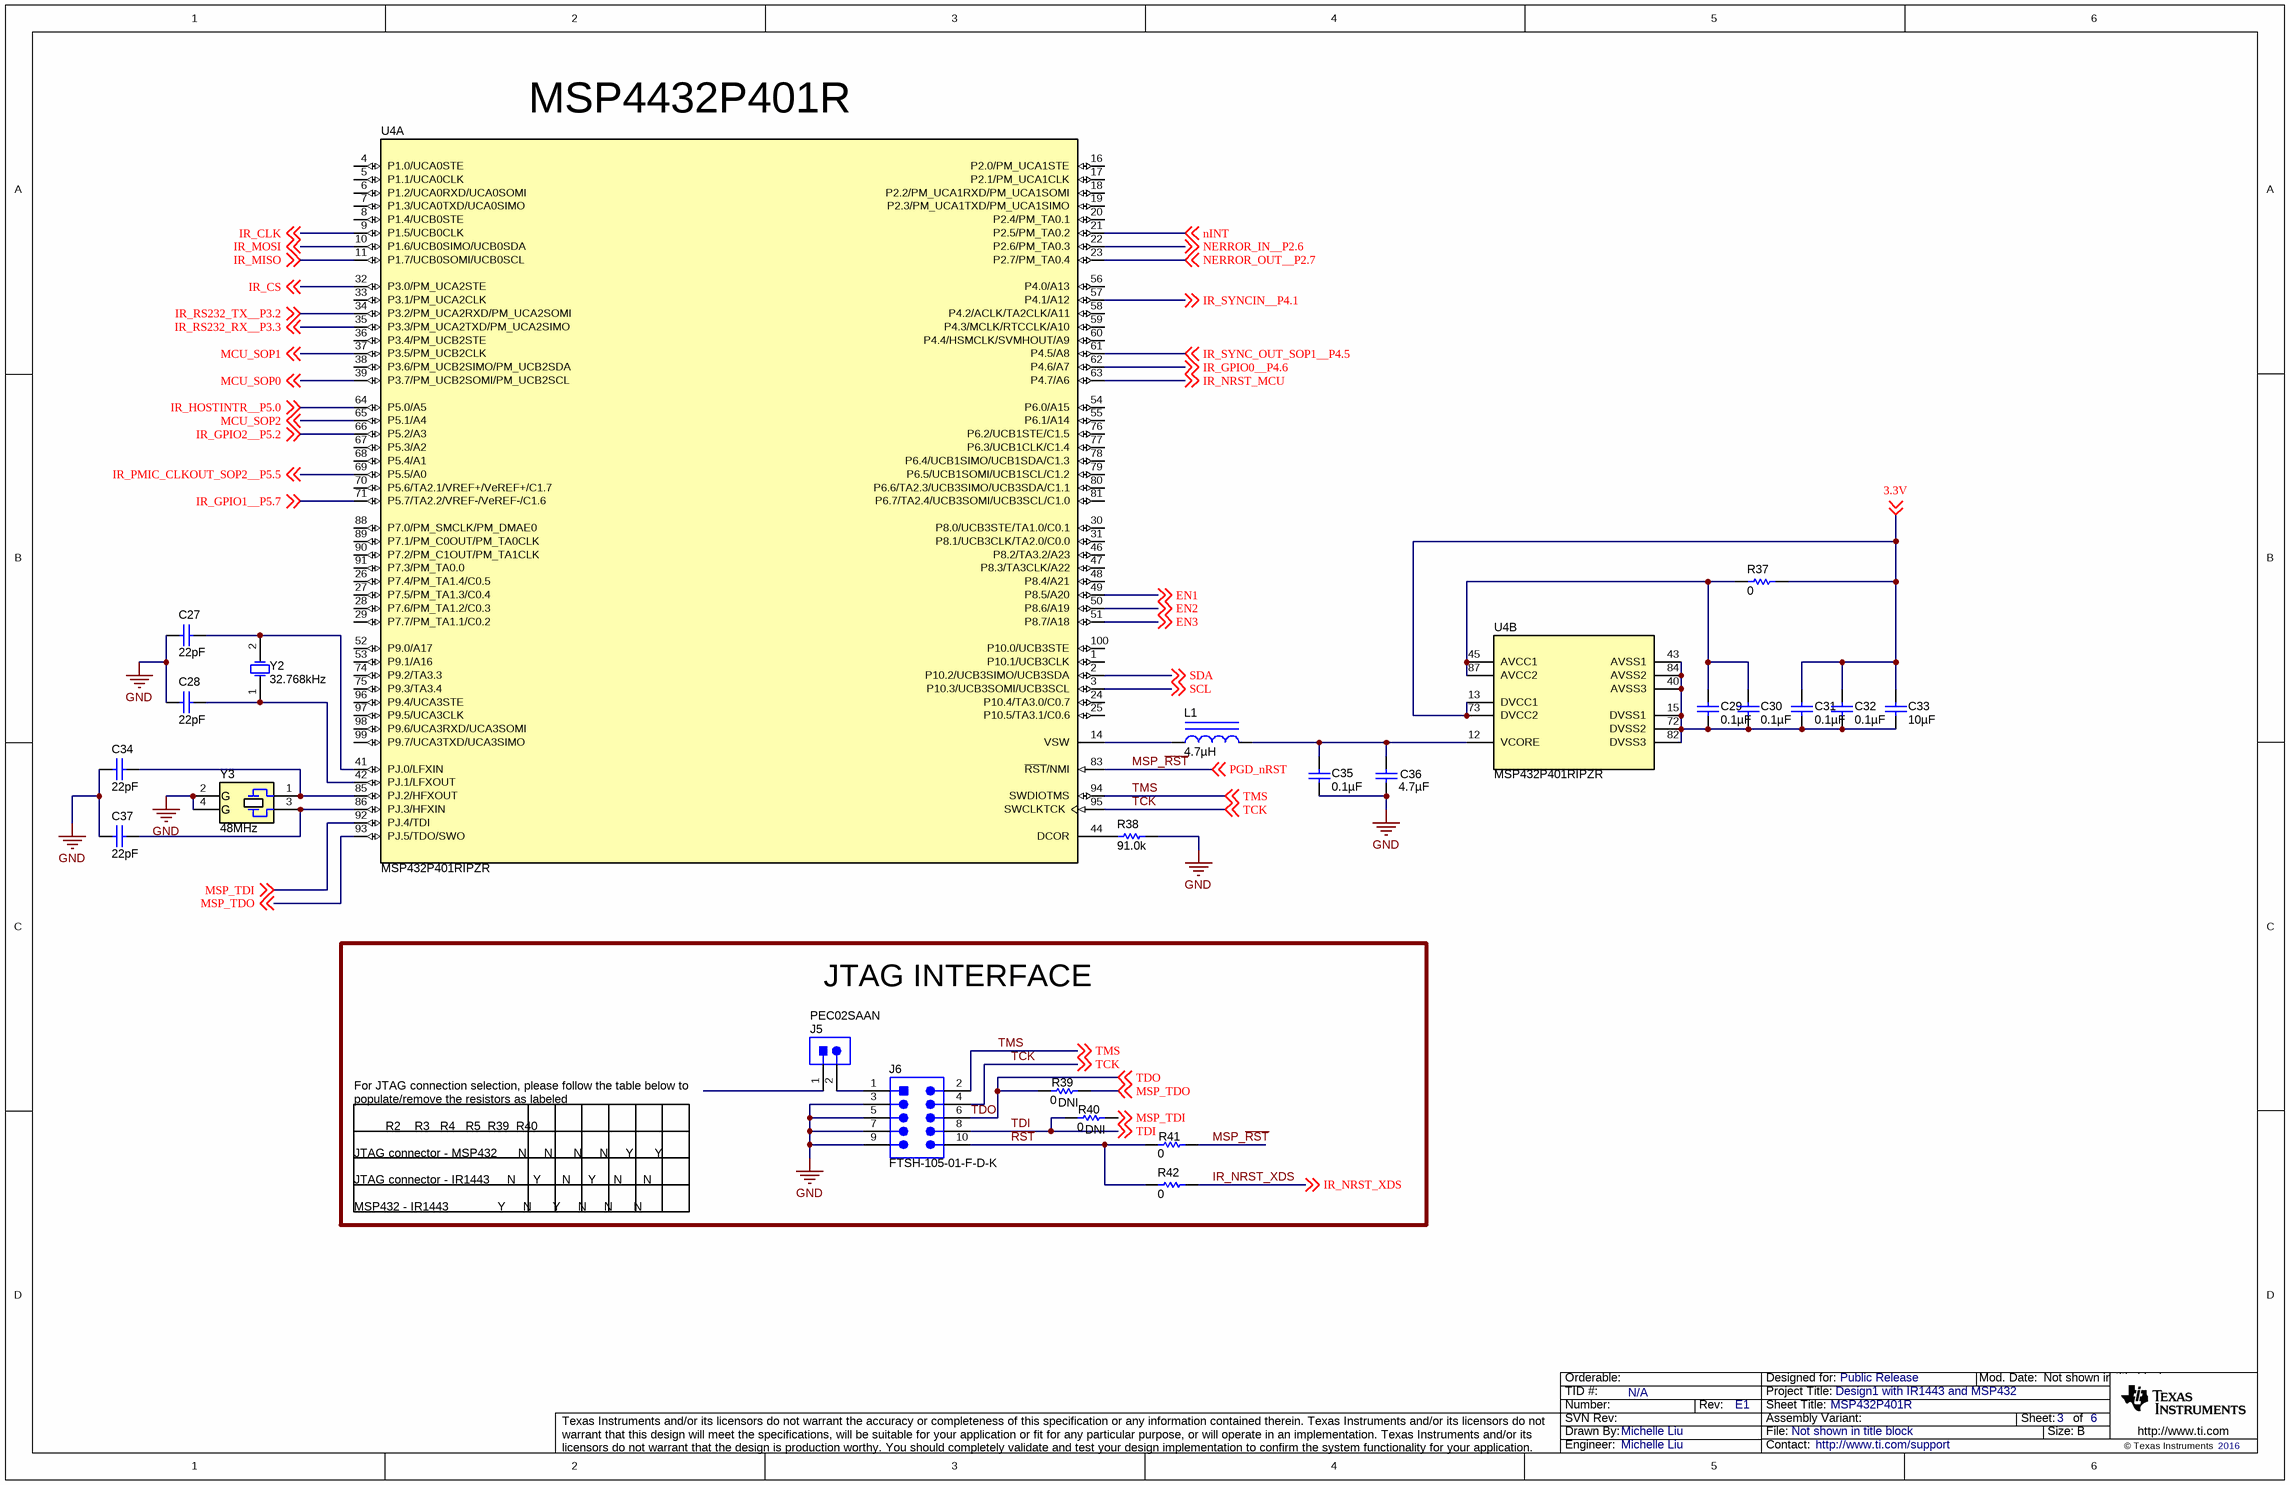
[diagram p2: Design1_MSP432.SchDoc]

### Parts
C27  ValueDisplayed: 22pF  [0402]  (hidden comment: C1005C0G1H220J050BA)
C28  ValueDisplayed: 22pF  [0402]  (hidden comment: C1005C0G1H220J050BA)
C29  ValueDisplayed: 0.1µF  [0402]  (hidden comment: CGA2B3X7R1H104K050BB)
C30  ValueDisplayed: 0.1µF  [0402]  (hidden comment: CGA2B3X7R1H104K050BB)
C31  ValueDisplayed: 0.1µF  [0402]  (hidden comment: CGA2B3X7R1H104K050BB)
C32  ValueDisplayed: 0.1µF  [0402]  (hidden comment: CGA2B3X7R1H104K050BB)
C33  ValueDisplayed: 10µF  [0805_HV]  (hidden comment: GCM21BR71A106KE22L)
C34  ValueDisplayed: 22pF  [0402]  (hidden comment: C1005C0G1H220J050BA)
C35  ValueDisplayed: 0.1µF  [0402]  (hidden comment: CGA2B3X7R1H104K050BB)
C36  ValueDisplayed: 4.7µF  [0805_HV]  (hidden comment: LMK212BJ475KD-T)
C37  ValueDisplayed: 22pF  [0402]  (hidden comment: C1005C0G1H220J050BA)
J5  PEC02SAAN  [CONN_PEC02SAAN]
J6  FTSH-105-01-F-D-K  [Samtec_FTSH-105-01-x-D-K]
L1  ValueDisplayed: 4.7µH  [0805_HV]  (hidden comment: BRC2012T4R7MD)
R37  ValueDisplayed: 0  [0402]  (hidden comment: ERJ-2GE0R00X)
R38  ValueDisplayed: 91.0k  [0805_HV]  (hidden comment: RG2012P-913-B-T5)
R39  DNI  ValueDisplayed: 0  [0402]
R40  DNI  ValueDisplayed: 0  [0402]
R41  ValueDisplayed: 0  [0402]  (hidden comment: RC0402JR-070RL)
R42  ValueDisplayed: 0  [0402]  (hidden comment: RC0402JR-070RL)
U4  MSP432P401RIPZR  [PZ0100A_N]  (parts A,B of 2)
Y2  Frequency: 32.768kHz  [Epson_FC-135]  (hidden comment: X1A0001410014)
Y3  Frequency: 48MHz  [Epson_FA-238]  (hidden comment: FA-238 48.0000MB-W0)

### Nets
3.3V: C31.1 C32.1 C33.1 J5.1 R37.2 U4.13(DVCC1) U4.73(DVCC2) ; off-sheet 3.3V
EN1: U4.49(P8.5/A20) ; off-sheet EN1
EN2: U4.50(P8.6/A19) ; off-sheet EN2
EN3: U4.51(P8.7/A18) ; off-sheet EN3
GND: C27.2 C28.2 C34.2 C35.2 C36.2 C37.2 J6.3 J6.5 J6.7 J6.9 R38.2 Y3.2(GND) Y3.4(GND)
IR_MISO: U4.11(P1.7/UCB0SOMI/UCB0SCL) ; off-sheet IR_MISO  [project net MISO]
IR_MOSI: U4.10(P1.6/UCB0SIMO/UCB0SDA) ; off-sheet IR_MOSI  [project net MOSI]
nINT: U4.21(P2.5/PM_TA0.2) ; off-sheet nINT
SCL: U4.3(P10.3/UCB3SOMI/UCB3SCL) ; off-sheet SCL
SDA: U4.2(P10.2/UCB3SIMO/UCB3SDA) ; off-sheet SDA
~{RST}: J6.10 R41.1 R42.1
IR_CLK: U4.9(P1.5/UCB0CLK) ; off-sheet IR_CLK
IR_CS: U4.32(P3.0/PM_UCA2STE) ; off-sheet IR_CS
IR_GPIO0__P4.6: U4.62(P4.6/A7) ; off-sheet IR_GPIO0__P4.6
IR_GPIO1__P5.7: U4.71(P5.7/TA2.2/VREF-/VeREF-/C1.6) ; off-sheet IR_GPIO1__P5.7
IR_GPIO2__P5.2: U4.66(P5.2/A3) ; off-sheet IR_GPIO2__P5.2
IR_HOSTINTR__P5.0: U4.64(P5.0/A5) ; off-sheet IR_HOSTINTR__P5.0
IR_NRST_MCU: U4.63(P4.7/A6) ; off-sheet IR_NRST_MCU
IR_NRST_XDS: R42.2 ; off-sheet IR_NRST_XDS
IR_PMIC_CLKOUT_SOP2__P5.5: U4.69(P5.5/A0) ; off-sheet IR_PMIC_CLKOUT_SOP2__P5.5
IR_RS232_RX__P3.3: U4.35(P3.3/PM_UCA2TXD/PM_UCA2SIMO) ; off-sheet IR_RS232_RX__P3.3
IR_RS232_TX__P3.2: U4.34(P3.2/PM_UCA2RXD/PM_UCA2SOMI) ; off-sheet IR_RS232_TX__P3.2
IR_SYNC_OUT_SOP1__P4.5: U4.61(P4.5/A8) ; off-sheet IR_SYNC_OUT_SOP1__P4.5
IR_SYNCIN__P4.1: U4.57(P4.1/A12) ; off-sheet IR_SYNCIN__P4.1
MCU_SOP0: U4.39(P3.7/PM_UCB2SOMI/PM_UCB2SCL) ; off-sheet MCU_SOP0
MCU_SOP1: U4.37(P3.5/PM_UCB2CLK) ; off-sheet MCU_SOP1
MCU_SOP2: U4.65(P5.1/A4) ; off-sheet MCU_SOP2
MSP_~{RST}: R41.2 U4.83(~{RST}/NMI) ; off-sheet PGD_nRST  [also labelled PGD_nRST]
MSP_TDI: R40.2 U4.92(PJ.4/TDI) ; off-sheet MSP_TDI
MSP_TDO: R39.2 U4.93(PJ.5/TDO/SWO) ; off-sheet MSP_TDO
NERROR_IN__P2.6: U4.22(P2.6/PM_TA0.3) ; off-sheet NERROR_IN__P2.6
NERROR_OUT__P2.7: U4.23(P2.7/PM_TA0.4) ; off-sheet NERROR_OUT__P2.7
TCK: J6.4 U4.95(SWCLKTCK) ; off-sheet TCK
TDI: J6.8 R40.1 ; off-sheet TDI
TDO: J6.6 R39.1 ; off-sheet TDO
TMS: J6.2 U4.94(SWDIOTMS) ; off-sheet TMS
NetC27_1: C27.1 U4.41(PJ.0/LFXIN) Y2.2(OSC2)
NetC28_1: C28.1 U4.42(PJ.1/LFXOUT) Y2.1(OSC1)
NetC29_1: C29.1 C30.1 R37.1 U4.45(AVCC1) U4.87(AVCC2)
NetC29_2: C29.2 C30.2 C31.2 C32.2 C33.2 U4.15(DVSS1) U4.40(AVSS3) U4.43(AVSS1) U4.72(DVSS2) U4.82(DVSS3) U4.84(AVSS2)
NetC34_1: C34.1 U4.85(PJ.2/HFXOUT) Y3.1
NetC35_1: C35.1 C36.1 L1.2 U4.12(VCORE)
NetC37_1: C37.1 U4.86(PJ.3/HFXIN) Y3.3
NetJ5_2: J5.2 J6.1
NetL1_1: L1.1 U4.14(VSW)
NetR38_1: R38.1 U4.44(DCOR)

Not connected (* = marked no-connect by the designer): U4 1(P10.1/UCB3CLK) 4(P1.0/UCA0STE) 5(P1.1/UCA0CLK) 6(P1.2/UCA0RXD/UCA0SOMI) 7(P1.3/UCA0TXD/UCA0SIMO) 8(P1.4/UCB0STE) 16(P2.0/PM_UCA1STE) 17(P2.1/PM_UCA1CLK) 18(P2.2/PM_UCA1RXD/PM_UCA1SOMI) 19(P2.3/PM_UCA1TXD/PM_UCA1SIMO) 20(P2.4/PM_TA0.1) 24(P10.4/TA3.0/C0.7) 25(P10.5/TA3.1/C0.6) 26(P7.4/PM_TA1.4/C0.5) 27(P7.5/PM_TA1.3/C0.4) 28(P7.6/PM_TA1.2/C0.3) 29(P7.7/PM_TA1.1/C0.2) 30(P8.0/UCB3STE/TA1.0/C0.1) 31(P8.1/UCB3CLK/TA2.0/C0.0) 33(P3.1/PM_UCA2CLK) 36(P3.4/PM_UCB2STE) 38(P3.6/PM_UCB2SIMO/PM_UCB2SDA) 46(P8.2/TA3.2/A23) 47(P8.3/TA3CLK/A22) 48(P8.4/A21) 52(P9.0/A17) 53(P9.1/A16) 54(P6.0/A15) 55(P6.1/A14) 56(P4.0/A13) 58(P4.2/ACLK/TA2CLK/A11) 59(P4.3/MCLK/RTCCLK/A10) 60(P4.4/HSMCLK/SVMHOUT/A9) 67(P5.3/A2) 68(P5.4/A1) 70(P5.6/TA2.1/VREF+/VeREF+/C1.7) 74(P9.2/TA3.3) 75(P9.3/TA3.4) 76(P6.2/UCB1STE/C1.5) 77(P6.3/UCB1CLK/C1.4) 78(P6.4/UCB1SIMO/UCB1SDA/C1.3) 79(P6.5/UCB1SOMI/UCB1SCL/C1.2) 80(P6.6/TA2.3/UCB3SIMO/UCB3SDA/C1.1) 81(P6.7/TA2.4/UCB3SOMI/UCB3SCL/C1.0) 88(P7.0/PM_SMCLK/PM_DMAE0) 89(P7.1/PM_C0OUT/PM_TA0CLK) 90(P7.2/PM_C1OUT/PM_TA1CLK) 91(P7.3/PM_TA0.0) 96(P9.4/UCA3STE) 97(P9.5/UCA3CLK) 98(P9.6/UCA3RXD/UCA3SOMI) 99(P9.7/UCA3TXD/UCA3SIMO) 100(P10.0/UCB3STE)

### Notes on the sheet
- (near U4) MSP4432P401R
- JTAG INTERFACE
- For JTAG connection selection, please follow the table below to populate/remove the resistors as labeled
  R2    R3   R4   R5  R39  R40
  JTAG connector - MSP432 	    N     N      N     N     Y      Y
  JTAG connector - IR1443	    N     Y      N     Y     N      N
  MSP432 - IR1443    	    	    Y     N      Y     N     N      N

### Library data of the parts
C27 C28 C34 C37 = C1005C0G1H220J050BA: CAP, CERM, 22 pF, 50 V, +/- 5%, C0G/NP0, 0402; Manufacturer: TDK; Polarized: N; CompType: Capacitor; Value: 22pF; U/M: EA; Cap_F: 0.000000000022; Tolerance_%: 5; Value1: Unknown; VDC_V: 50; Value2: 50V; TaMin_C: -55; TaMax_C: 125; SizeArea_mm2: 0.5; SizeAreaWB_mm2: 3; SizeX_mm: 1; SizeZ_mm: 0.6; AEC Category: Q200
C29-C32 C35 = CGA2B3X7R1H104K050BB: as C23 on sheet Design1_IWR1443_interfaces
C33 = GCM21BR71A106KE22L: as C9 on sheet Design1_IWR1443_interfaces
C36 = LMK212BJ475KD-T: CAP, CERM, 4.7 µF, 10 V, +/- 10%, X5R, 0805; Manufacturer: Taiyo Yuden; Polarized: N; CompType: Capacitor; Value: 4.7uF; U/M: EA; Cap_F: 0.0000047; Tolerance_%: 10; Value1: Unknown; Value2: 10V; TaMin_C: -55; TaMax_C: 85; Cap_Case: 0805; SizeArea_mm2: 2.5; SizeAreaWB_mm2: 6.75; SizeX_mm: 2; SizeY_mm: 1.25; SizeZ_mm: 1.45; AEC Category: Q200
J5 = PEC02SAAN: as J2 on sheet Design1_IWR1443_interfaces
J6 = FTSH-105-01-F-D-K: Header, 1.27 mm, 5x2, Gold, TH; Manufacturer: Samtec; SymbolCreator: a0412235; Pitch_mm: 1.27; Gender: Male; Shrouded: Y; Row_Count: 2
L1 = BRC2012T4R7MD: Inductor, Wirewound, 4.7 µH, 0.6 A, 0.265 ohm, SMD; Manufacturer: Taiyo Yuden; Value: 4.7uH; Ind_H: 4.7E-6; Imax_A: 0.6; Irms: 0.6A @ 40C rise; Isat: 0.7A @ 30% inductance drop; DCR_ohm: 0.265; Value2: 0.6A; SizeAreaWB_mm2: 6.75; SizeArea_mm2: 2.5; SizeX_mm: 2; SizeY_mm: 1.25; SizeZ_mm: 1.45; AEC Category: Q200; AEC Qualified: N
R37 R39 R40 = ERJ-2GE0R00X: RES, 0, 5%, 0.063 W, 0402; Manufacturer: Panasonic; CompType: Resistor; Value: 0; Value_Code: 0000; Tolerance_%: 5; Power_W: 0.063; Value2: 0.063W; VDC_V: 50; TempCo: 600 ppm/C; SizeArea_mm2: 0.5; SizeX_mm: 1; SizeZ_mm: 0.6; EIA_Code: E24; U/M: EA; AEC Category: Q200
R38 = RG2012P-913-B-T5: RES, 91.0 k, 0.1%, 0.125 W, 0805; Manufacturer: Susumu Co Ltd; CompType: Resistor; Value: 91.0k; Res_ohm: 91000; Value_Code: 91k0; Tolerance_%: 0.1; Power_W: 0.125; Value2: 0.125W; VDC_V: 100; TempCo: 25 ppm/C; SizeArea_mm2: 2.5; SizeX_mm: 2; SizeY_mm: 1.25; SizeZ_mm: 1.45; U/M: EA; AEC Category: Q200
R41 R42 = RC0402JR-070RL: as R2 on sheet Design1_IWR1443_interfaces
U4 = MSP432P401RIPZR: Mixed-Signal Microcontroller, PZ0100A (LQFP-100); Manufacturer: Texas Instruments; SymbolCreator: Altium; SizeArea_mm2: 256; SizeAreaWB_mm2: 324; SizeX_mm: 16; SizeZ_mm: 1.6; CompType: IC; U/M: EA
Y2 = X1A0001410014: Crystal, 32.768 KHz, 12.5 pF, SMD; Manufacturer: Epson; SymbolCreator: a0412235; U/M: EA; TaMin_C: -40; TaMax_C: 85
Y3 = FA-238 48.0000MB-W0: Crystal, 48MHz, 12pF, SMD; Manufacturer: Epson; SymbolCreator: a0412235; SizeAreaWB_mm2: 14.7; SizeArea_mm2: 8; SizeX_mm: 2.5; SizeY_mm: 3.2; SizeZ_mm: 0.7; U/M: EA; TaMin_C: -20; TaMax_C: 70; Frequency Stability: ±30ppm

## Sheet Design1_LowVoltage.SchDoc: Low Voltage Management
size 431 x 279 mm; Date: Not shown in title block; ApprovedBy: Not shown in title block; CheckedBy: Not shown in title block; Author: Not shown in title block; CompanyName: Not shown in title block; DrawnBy: Joe Quintal; Engineer: Joe Quintal; Organization: Not shown in title block; Address1: Not shown in title block; Address2: Not shown in title block; Address3: Not shown in title block; Address4: Not shown in title block; DocumentNumber: 4; Revision: Use project parameter SCH_Rev; SheetNumber: 4; SheetTotal: 6; PageSetup: Record=PageOptions¦CenterHorizontal=True¦CenterVertical=True¦PrintScale=0.64¦XCorrection=1.00¦YCorrection=1.00¦PrintKind=0¦BorderSize=5000000¦LeftOffset=0¦BottomOffset=0¦Orientation=2¦PaperLength=1000¦PaperWidth=1000¦Scale=100¦PaperSource=15¦PrintQuality=600¦MediaType=1¦DitherType=10¦PrintScaleMode=1¦PaperKind=Letter
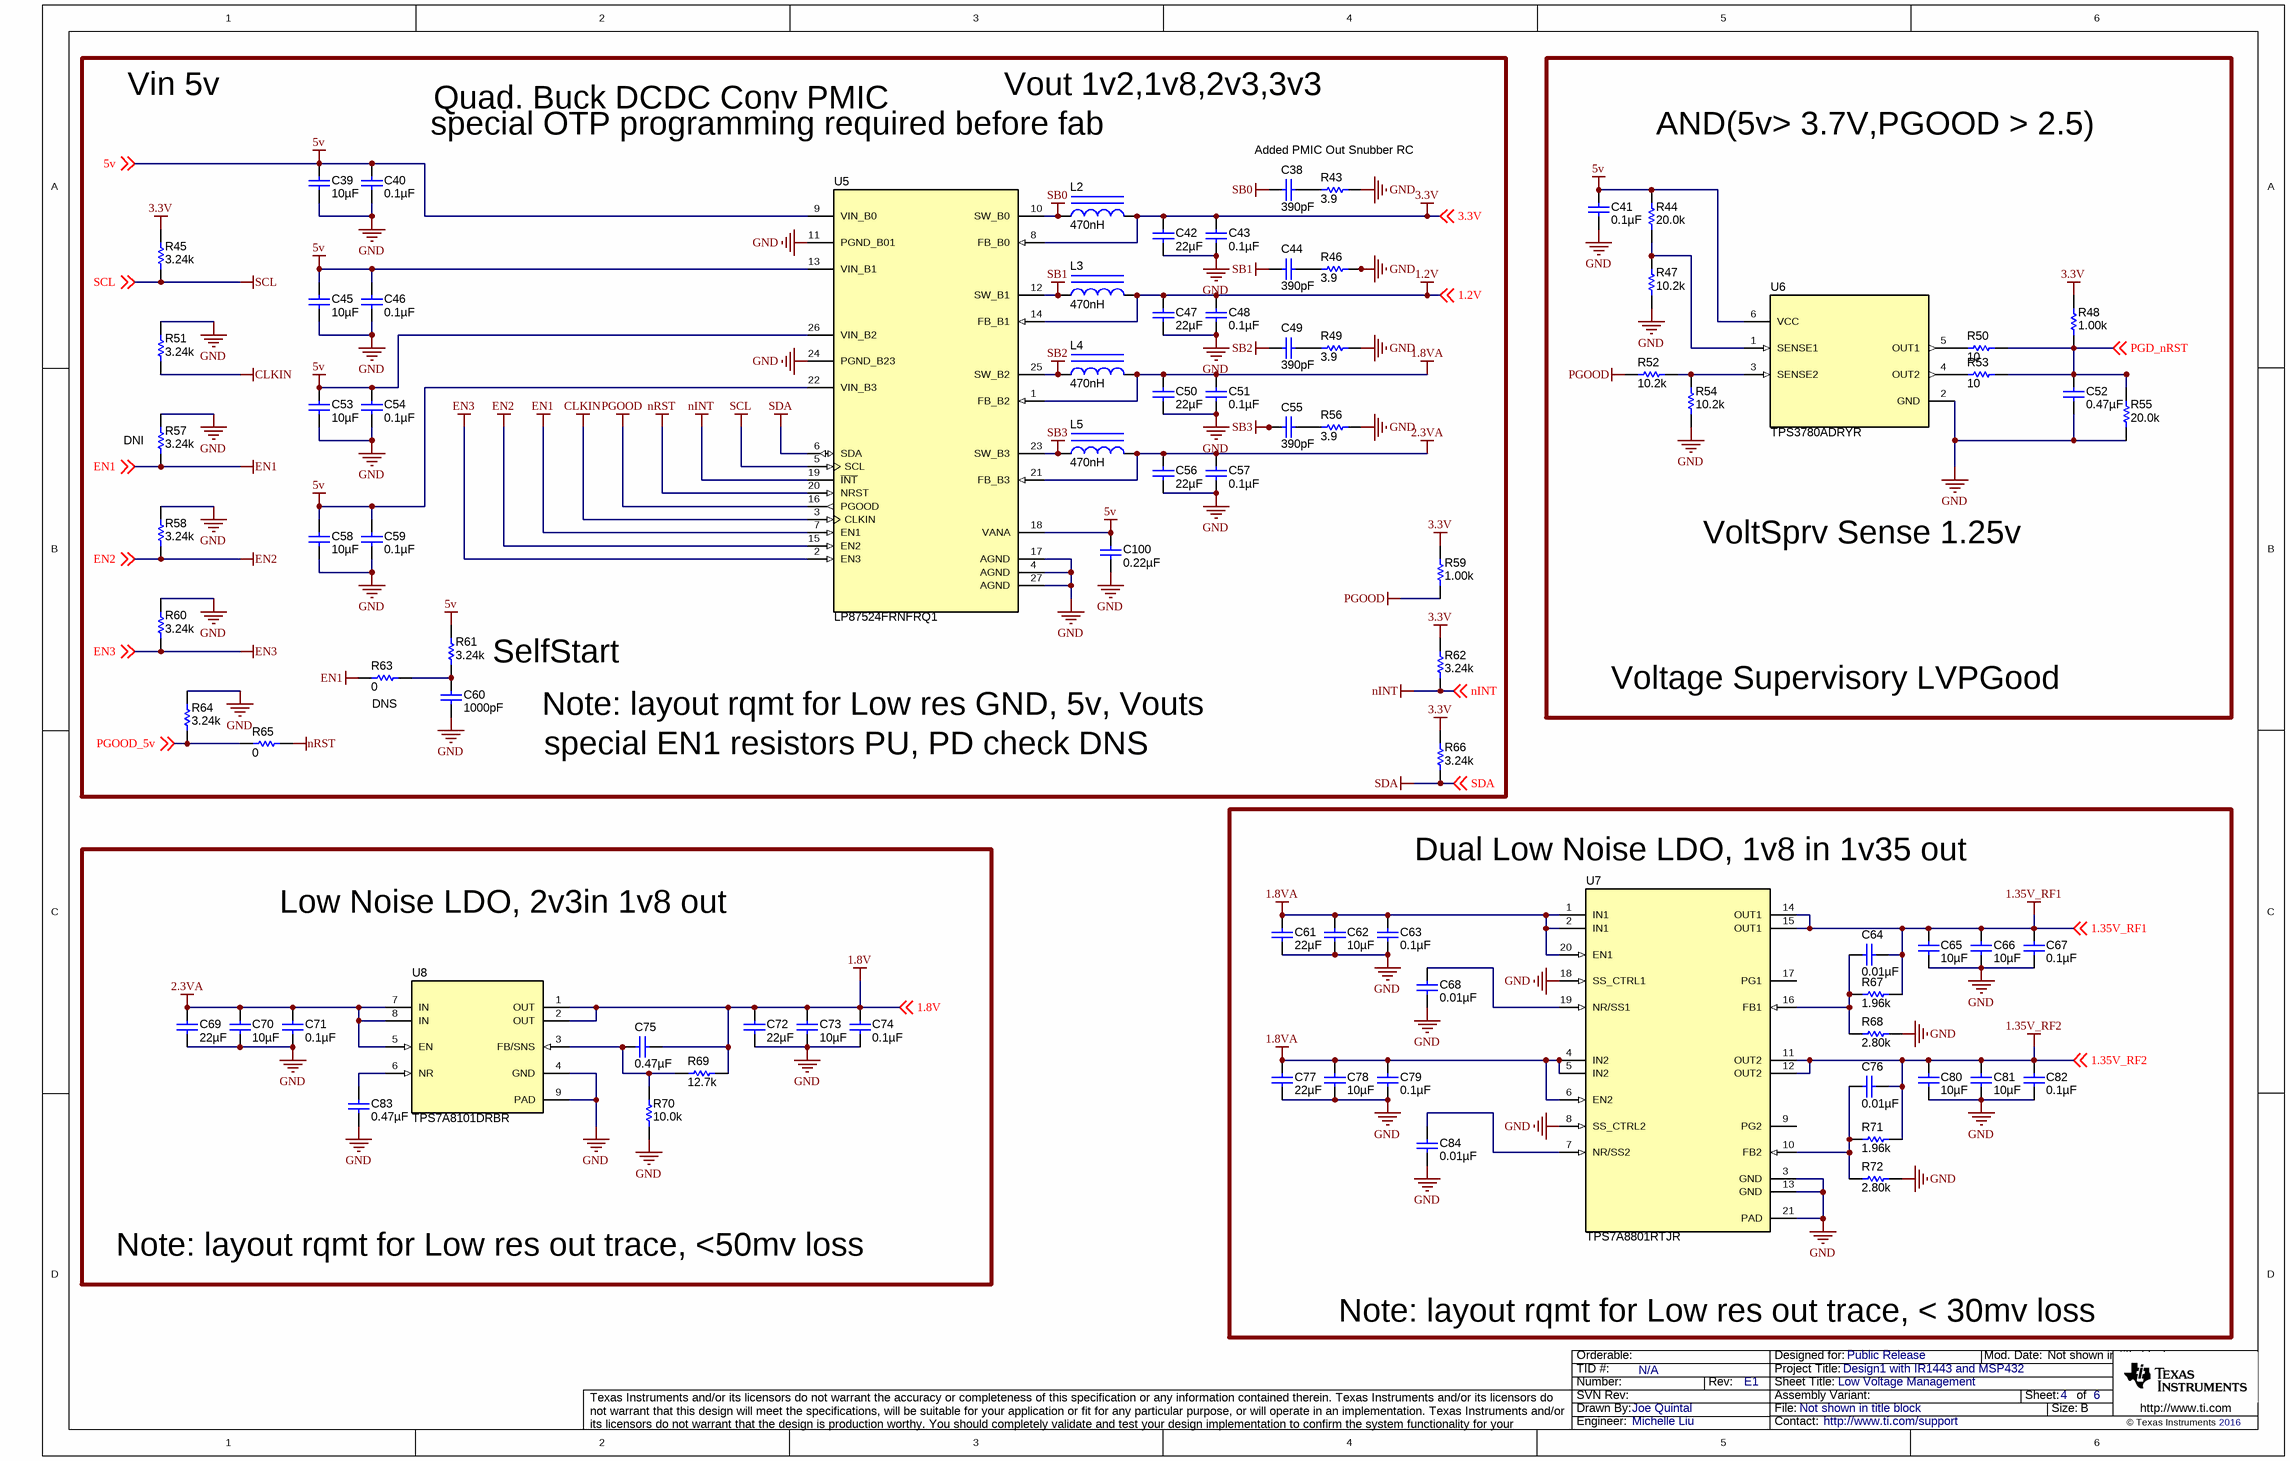
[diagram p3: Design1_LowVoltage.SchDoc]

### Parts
C38  ValueDisplayed: 390pF  [0603]  (hidden comment: 06035A391JAT2A)
C39  ValueDisplayed: 10µF  [0805_HV]  (hidden comment: C0805C106M8PACTU)
C40  ValueDisplayed: 0.1µF  [0402]  (hidden comment: GRM155R61A104KA01D)
C41  ValueDisplayed: 0.1µF  [0402]  (hidden comment: GRM155R61A104KA01D)
C42  ValueDisplayed: 22µF  [1206_180]  (hidden comment: GRM31CR61C226ME15L)
C43  ValueDisplayed: 0.1µF  [0402]  (hidden comment: GRM155R61A104KA01D)
C44  ValueDisplayed: 390pF  [0603]  (hidden comment: 06035A391JAT2A)
C45  ValueDisplayed: 10µF  [0805_HV]  (hidden comment: C0805C106M8PACTU)
C46  ValueDisplayed: 0.1µF  [0402]  (hidden comment: GRM155R61A104KA01D)
C47  ValueDisplayed: 22µF  [1206_180]  (hidden comment: GRM31CR61C226ME15L)
C48  ValueDisplayed: 0.1µF  [0402]  (hidden comment: GRM155R61A104KA01D)
C49  ValueDisplayed: 390pF  [0603]  (hidden comment: 06035A391JAT2A)
C50  ValueDisplayed: 22µF  [1206_180]  (hidden comment: GRM31CR61C226ME15L)
C51  ValueDisplayed: 0.1µF  [0402]  (hidden comment: GRM155R61A104KA01D)
C52  ValueDisplayed: 0.47µF  [0508]  (hidden comment: LLL219R71A474MA01L)
C53  ValueDisplayed: 10µF  [0805_HV]  (hidden comment: C0805C106M8PACTU)
C54  ValueDisplayed: 0.1µF  [0402]  (hidden comment: GRM155R61A104KA01D)
C55  ValueDisplayed: 390pF  [0603]  (hidden comment: 06035A391JAT2A)
C56  ValueDisplayed: 22µF  [1206_180]  (hidden comment: GRM31CR61C226ME15L)
C57  ValueDisplayed: 0.1µF  [0402]  (hidden comment: GRM155R61A104KA01D)
C58  ValueDisplayed: 10µF  [0805_HV]  (hidden comment: C0805C106M8PACTU)
C59  ValueDisplayed: 0.1µF  [0402]  (hidden comment: GRM155R61A104KA01D)
C60  ValueDisplayed: 1000pF  [0603]  (hidden comment: GRM188R71C102KA01D)
C61  ValueDisplayed: 22µF  [1206_180]  (hidden comment: GRM31CR61C226ME15L)
C62  ValueDisplayed: 10µF  [0805_HV]  (hidden comment: C0805C106M8PACTU)
C63  ValueDisplayed: 0.1µF  [0402]  (hidden comment: GRM155R61A104KA01D)
C64  ValueDisplayed: 0.01µF  [0603]  (hidden comment: C1608X7R1H103K080AA)
C65  ValueDisplayed: 10µF  [0805_HV]  (hidden comment: C0805C106M8PACTU)
C66  ValueDisplayed: 10µF  [0805_HV]  (hidden comment: C0805C106M8PACTU)
C67  ValueDisplayed: 0.1µF  [0402]  (hidden comment: GRM155R61A104KA01D)
C68  ValueDisplayed: 0.01µF  [0603]  (hidden comment: C1608X7R1H103K080AA)
C69  ValueDisplayed: 22µF  [1206_180]  (hidden comment: GRM31CR61C226ME15L)
C70  ValueDisplayed: 10µF  [0805_HV]  (hidden comment: C0805C106M8PACTU)
C71  ValueDisplayed: 0.1µF  [0402]  (hidden comment: GRM155R61A104KA01D)
C72  ValueDisplayed: 22µF  [1206_180]  (hidden comment: GRM31CR61C226ME15L)
C73  ValueDisplayed: 10µF  [0805_HV]  (hidden comment: C0805C106M8PACTU)
C74  ValueDisplayed: 0.1µF  [0402]  (hidden comment: GRM155R61A104KA01D)
C75  ValueDisplayed: 0.47µF  [0508]  (hidden comment: LLL219R71A474MA01L)
C76  ValueDisplayed: 0.01µF  [0603]  (hidden comment: C1608X7R1H103K080AA)
C77  ValueDisplayed: 22µF  [1206_180]  (hidden comment: GRM31CR61C226ME15L)
C78  ValueDisplayed: 10µF  [0805_HV]  (hidden comment: C0805C106M8PACTU)
C79  ValueDisplayed: 0.1µF  [0402]  (hidden comment: GRM155R61A104KA01D)
C80  ValueDisplayed: 10µF  [0805_HV]  (hidden comment: C0805C106M8PACTU)
C81  ValueDisplayed: 10µF  [0805_HV]  (hidden comment: C0805C106M8PACTU)
C82  ValueDisplayed: 0.1µF  [0402]  (hidden comment: GRM155R61A104KA01D)
C83  ValueDisplayed: 0.47µF  [0508]  (hidden comment: LLL219R71A474MA01L)
C84  ValueDisplayed: 0.01µF  [0603]  (hidden comment: C1608X7R1H103K080AA)
C100  ValueDisplayed: 0.22µF  [0603]  (hidden comment: GCM155R71C224KE02)
L2  ValueDisplayed: 470nH  [IHLP-1616AB]  (hidden comment: IHLP1616ABERR47M01)
L3  ValueDisplayed: 470nH  [IHLP-1616AB]  (hidden comment: IHLP1616ABERR47M01)
L4  ValueDisplayed: 470nH  [IHLP-1616AB]  (hidden comment: IHLP1616ABERR47M01)
L5  ValueDisplayed: 470nH  [IHLP-1616AB]  (hidden comment: IHLP1616ABERR47M01)
R43  ValueDisplayed: 3.9  [0402]  (hidden comment: CRCW04023R90JNED)
R44  ValueDisplayed: 20.0k  [0603]  (hidden comment: CRCW060320K0FKEA)
R45  ValueDisplayed: 3.24k  [0603]  (hidden comment: CRCW06033K24FKEA)
R46  ValueDisplayed: 3.9  [0402]  (hidden comment: CRCW04023R90JNED)
R47  ValueDisplayed: 10.2k  [0603]  (hidden comment: CRCW060310K2FKEA)
R48  ValueDisplayed: 1.00k  [0603]  (hidden comment: CRCW06031K00FKEA)
R49  ValueDisplayed: 3.9  [0402]  (hidden comment: CRCW04023R90JNED)
R50  ValueDisplayed: 10  [0603]  (hidden comment: CRCW060310R0JNEA)
R51  ValueDisplayed: 3.24k  [0603]  (hidden comment: CRCW06033K24FKEA)
R52  ValueDisplayed: 10.2k  [0603]  (hidden comment: CRCW060310K2FKEA)
R53  ValueDisplayed: 10  [0603]  (hidden comment: CRCW060310R0JNEA)
R54  ValueDisplayed: 10.2k  [0603]  (hidden comment: CRCW060310K2FKEA)
R55  ValueDisplayed: 20.0k  [0603]  (hidden comment: CRCW060320K0FKEA)
R56  ValueDisplayed: 3.9  [0402]  (hidden comment: CRCW04023R90JNED)
R57  ValueDisplayed: 3.24k  [0603]  (hidden comment: CRCW06033K24FKEA)
R58  ValueDisplayed: 3.24k  [0603]  (hidden comment: CRCW06033K24FKEA)
R59  ValueDisplayed: 1.00k  [0603]  (hidden comment: CRCW06031K00FKEA)
R60  ValueDisplayed: 3.24k  [0603]  (hidden comment: CRCW06033K24FKEA)
R61  ValueDisplayed: 3.24k  [0603]  (hidden comment: CRCW06033K24FKEA)
R62  ValueDisplayed: 3.24k  [0603]  (hidden comment: CRCW06033K24FKEA)
R63  ValueDisplayed: 0  [0603]  (hidden comment: ERJ-3GEY0R00V)
R64  ValueDisplayed: 3.24k  [0603]  (hidden comment: CRCW06033K24FKEA)
R65  ValueDisplayed: 0  [0603]  (hidden comment: ERJ-3GEY0R00V)
R66  ValueDisplayed: 3.24k  [0603]  (hidden comment: CRCW06033K24FKEA)
R67  ValueDisplayed: 1.96k  [0603]  (hidden comment: RT0603DRE071K96L)
R68  ValueDisplayed: 2.80k  [0603]  (hidden comment: RT0603DRE072K8L)
R69  ValueDisplayed: 12.7k  [0603]  (hidden comment: RT0603BRD0712K7L)
R70  ValueDisplayed: 10.0k  [0603]  (hidden comment: CRCW060310K0FKEA)
R71  ValueDisplayed: 1.96k  [0603]  (hidden comment: RT0603DRE071K96L)
R72  ValueDisplayed: 2.80k  [0603]  (hidden comment: RT0603DRE072K8L)
U5  LP87524FRNFRQ1  [RNF0026C]
U6  TPS3780ADRYR  [DRY0006A]
U7  TPS7A8801RTJR  [RTJ0020D]
U8  TPS7A8101DRBR  [DRB0008A]

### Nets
1.2V: C47.1 C48.1 L3.2 U5.14(FB_B1) ; off-sheet 1.2V
1.8V: C72.1 C73.2 C74.1 C75.2 R69.2 U8.1(OUT) U8.2(OUT) ; off-sheet 1.8V
1.8VA: C50.1 C51.1 C61.1 C62.2 C63.1 C77.1 C78.2 C79.1 L4.2 U5.1(FB_B2) U7.1(IN1) U7.2(IN1) U7.4(IN2) U7.5(IN2) U7.6(EN2) U7.20(EN1)
1.35V_RF1: C64.1 C65.2 C66.2 C67.1 R67.2 U7.14(OUT1) U7.15(OUT1) ; off-sheet 1.35V_RF1
1.35V_RF2: C76.1 C80.2 C81.2 C82.1 R71.2 U7.11(OUT2) U7.12(OUT2) ; off-sheet 1.35V_RF2
2.3VA: C56.1 C57.1 C69.1 C70.2 C71.1 L5.2 U5.21(FB_B3) U8.5(EN) U8.7(IN) U8.8(IN)
3.3V: C42.1 C43.1 L2.2 R45.2 R48.2 R59.2 R62.2 R66.2 U5.8(FB_B0) ; off-sheet 3.3V
5v: C39.2 C40.1 C41.1 C45.2 C46.1 C53.2 C54.1 C58.2 C59.1 C100.1 R44.2 R61.2 U5.9(VIN_B0) U5.13(VIN_B1) U5.18(VANA) U5.22(VIN_B3) U5.26(VIN_B2) U6.6(VCC) ; off-sheet 5v
CLKIN: R51.1 U5.3(CLKIN)
EN1: R57.1 R63.1 U5.7(EN1) ; off-sheet EN1
EN2: R58.1 U5.15(EN2) ; off-sheet EN2
EN3: R60.1 U5.2(EN3) ; off-sheet EN3
GND: C39.1 C40.2 C41.2 C42.2 C43.2 C45.1 C46.2 C47.2 C48.2 C50.2 C51.2 C52.2 C53.1 C54.2 C56.2 C57.2 C58.1 C59.2 C60.2 C61.2 C62.1 C63.2 C65.1 C66.1 C67.2 C68.2 C69.2 C70.1 C71.2 C72.2 C73.1 C74.2 C77.2 C78.1 C79.2 C80.1 C81.1 C82.2 C83.2 C84.2 C100.2 R43.2 R46.2 R47.1 R49.2 R51.2 R54.1 R55.1 R56.2 R57.2 R58.2 R60.2 R64.2 R68.2 R70.1 R72.2 U5.4(AGND) U5.11(PGND_B01) U5.17(AGND) U5.24(PGND_B23) U5.27(AGND) U6.2(GND) U7.3(GND) U7.8(SS_CTRL2) U7.13(GND) U7.18(SS_CTRL1) U7.21(PAD) U8.4(GND) U8.9(PAD)
nINT: R62.1 U5.19(~{INT}) ; off-sheet nINT
nRST: R65.2 U5.20(NRST)
PGOOD: R52.1 R59.1 U5.16(PGOOD)
PGOOD_5v: R64.1 R65.1 ; off-sheet PGOOD_5v
SB0: C38.2 L2.1 U5.10(SW_B0)
SB1: C44.2 L3.1 U5.12(SW_B1)
SB2: C49.2 L4.1 U5.25(SW_B2)
SB3: C55.2 L5.1 U5.23(SW_B3)
SCL: R45.1 U5.5(SCL) ; off-sheet SCL
SDA: R66.1 U5.6(SDA) ; off-sheet SDA
PGD_nRST: C52.1 R48.1 R50.2 R53.2 R55.2 ; off-sheet PGD_nRST  [project net MSP_~{RST}]
NetC38_1: C38.1 R43.1
NetC44_1: C44.1 R46.1
NetC49_1: C49.1 R49.1
NetC55_1: C55.1 R56.1
NetC60_1: C60.1 R61.1 R63.2
NetC64_2: C64.2 R67.1 R68.1 U7.16(FB1)
NetC68_1: C68.1 U7.19(NR/SS1)
NetC75_1: C75.1 R69.1 R70.2 U8.3(FB/SNS)
NetC76_2: C76.2 R71.1 R72.1 U7.10(FB2)
NetC83_1: C83.1 U8.6(NR)
NetC84_1: C84.1 U7.7(NR/SS2)
NetR44_1: R44.1 R47.2 U6.1(SENSE1)
NetR50_1: R50.1 U6.5(OUT1)
NetR52_2: R52.2 R54.2 U6.3(SENSE2)
NetR53_1: R53.1 U6.4(OUT2)

Not connected (* = marked no-connect by the designer): U7 9(PG2) 17(PG1)

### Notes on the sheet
- Vin 5v
- Quad. Buck DCDC Conv PMIC
- Vout 1v2,1v8,2v3,3v3
- special OTP programming required before fab
- Added PMIC Out Snubber RC
- AND(5v> 3.7V,PGOOD > 2.5)
- (near R57) DNI
- VoltSprv Sense 1.25v
- SelfStart
- Voltage Supervisory LVPGood
- (near R63) DNS
- special EN1 resistors PU, PD check DNS
- Note: layout rqmt for Low res GND, 5v, Vouts
- Dual Low Noise LDO, 1v8 in 1v35 out
- Low Noise LDO, 2v3in 1v8 out
- Note: layout rqmt for Low res out trace, <50mv loss
- Note: layout rqmt for Low res out trace, < 30mv loss

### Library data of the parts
C38 C44 C49 C55 = 06035A391JAT2A: CAP, CERM, 390 pF, 50 V, +/- 5%, C0G/NP0, 0603; Manufacturer: AVX; Polarized: N; CompType: Capacitor; Value: 390pF; U/M: EA; Cap_F: 0.00000000039; Tolerance_%: 5; ESR_ohm: 0.067; Value1: 0.067 ohm; VDC_V: 50; Value2: 50V; TaMin_C: -55; TaMax_C: 125; SizeArea_mm2: 1.28; SizeAreaWB_mm2: 4.68; SizeX_mm: 1.6; SizeY_mm: 0.8; SizeZ_mm: 1; AEC Category: Q200
C39 C45 C53 C58 C62 C65 C66 C70 C73 C78 C80 C81 = C0805C106M8PACTU: CAP, CERM, 10 µF, 10 V, +/- 20%, X5R, 0805; Manufacturer: Kemet; Polarized: N; CompType: Capacitor; Value: 10uF; U/M: EA; Cap_F: 0.00001; Tolerance_%: 20; ESR_ohm: 0.003; Value1: 0.003 ohm; VDC_V: 10; Value2: 10V; IRMS_A: 11.43; TaMin_C: -55; TaMax_C: 85; Cap_Case: 0805; SizeArea_mm2: 2.5; SizeAreaWB_mm2: 6.75; SizeX_mm: 2; SizeY_mm: 1.25; SizeZ_mm: 1.45; AEC Category: Q200
C40 C41 C43 C46 C48 C51 C54 C57 C59 C63 C67 C71 C74 C79 C82 = GRM155R61A104KA01D: CAP, CERM, 0.1 µF, 10 V, +/- 10%, X5R, 0402; Manufacturer: MuRata; Polarized: N; CompType: Capacitor; Value: 0.1uF; U/M: EA; Cap_F: 0.0000001; Tolerance_%: 10; Value1: Unknown; Value2: 10V; TaMin_C: -55; TaMax_C: 85; SizeArea_mm2: 0.5; SizeAreaWB_mm2: 3; SizeX_mm: 1; SizeZ_mm: 0.6; AEC Category: Q200
C42 C47 C50 C56 C61 C69 C72 C77 = GRM31CR61C226ME15L: CAP, CERM, 22 µF, 16 V, +/- 20%, X5R, 1206; Manufacturer: MuRata; Polarized: N; CompType: Capacitor; Value: 22uF; U/M: EA; Cap_F: 0.000022; Tolerance_%: 20; ESR_ohm: 0.006; Value1: 0.006 ohm; VDC_V: 16; Value2: 16V; TaMin_C: -55; TaMax_C: 85; Cap_Case: 1206; SizeArea_mm2: 5.12; SizeAreaWB_mm2: 10.92; SizeX_mm: 3.2; SizeY_mm: 1.6; SizeZ_mm: 1.8; AEC Category: Q200
C52 C75 C83 = LLL219R71A474MA01L: CAP, CERM, 0.47 µF, 10 V, +/- 20%, X7R, 0508; Manufacturer: MuRata; Polarized: N; CompType: Capacitor; Value: 0.47uF; U/M: EA; Cap_F: 0.00000047; Tolerance_%: 20; Value1: Unknown; VDC_V: 10; Value2: 10V; TaMin_C: -55; TaMax_C: 125; SizeArea_mm2: 2.5; SizeAreaWB_mm2: 6.75; SizeX_mm: 1.25; SizeY_mm: 2; SizeZ_mm: 1; AEC Category: Q200
C60 = GRM188R71C102KA01D: CAP, CERM, 1000 pF, 16 V, +/- 10%, X7R, 0603; Manufacturer: MuRata; Polarized: N; CompType: Capacitor; Value: 1000pF; U/M: EA; Cap_F: 0.000000001; Tolerance_%: 10; Value1: Unknown; VDC_V: 16; Value2: 16V; TaMin_C: -55; TaMax_C: 125; SizeArea_mm2: 1.28; SizeAreaWB_mm2: 4.68; SizeX_mm: 1.6; SizeY_mm: 0.8; SizeZ_mm: 1; AEC Category: Q200
C64 C68 C76 C84 = C1608X7R1H103K080AA: CAP, CERM, 0.01 µF, 50 V, +/- 10%, X7R, 0603; Manufacturer: TDK; Polarized: N; CompType: Capacitor; Value: 0.01uF; U/M: EA; Cap_F: 0.00000001; Tolerance_%: 10; ESR_ohm: 0.0539; Value1: 0.0539 ohm; VDC_V: 50; Value2: 50V; TaMin_C: -55; TaMax_C: 125; SizeArea_mm2: 1.28; SizeAreaWB_mm2: 4.68; SizeX_mm: 1.6; SizeY_mm: 0.8; SizeZ_mm: 1; AEC Category: Q200
C100 = GCM155R71C224KE02: as C3 on sheet Design1_IWR1443_interfaces
L2-L5 = IHLP1616ABERR47M01: Inductor, Shielded Drum Core, Powdered Iron, 470 nH, 5 A, 0.02 ohm, SMD; Manufacturer: Vishay-Dale; Value: 470nH; Ind_H: 470.0E-9; Imax_A: 5; Irms: 5A @ 40C rise; Isat: 13A @ 20% inductance drop; DCR_ohm: 0.02; Value2: 5A; SizeAreaWB_mm2: 27.577; SizeArea_mm2: 18.067; SizeX_mm: 4.45; SizeY_mm: 4.06; SizeZ_mm: 1.2; AEC Category: Q200
R43 R46 R49 R56 = CRCW04023R90JNED: RES, 3.9, 5%, 0.063 W, 0402; Manufacturer: Vishay-Dale; CompType: Resistor; Value: 3.9; Value_Code: 3R90; Tolerance_%: 5; Power_W: 0.063; Value2: 0.063W; VDC_V: 50; TempCo: 200 ppm/C; SizeArea_mm2: 0.5; SizeX_mm: 1; SizeZ_mm: 0.6; EIA_Code: E24; U/M: EA; AEC Category: Q200
R44 R55 = CRCW060320K0FKEA: RES, 20.0 k, 1%, 0.1 W, 0603; Manufacturer: Vishay-Dale; CompType: Resistor; Value: 20.0k; Res_ohm: 20000; Value_Code: 20k0; Tolerance_%: 1; Power_W: 0.1; Value2: 0.1W; VDC_V: 75; TempCo: 100 ppm/C; SizeArea_mm2: 1.28; SizeX_mm: 1.6; SizeY_mm: 0.8; EIA_Code: E96; U/M: EA; AEC Category: Q200
R45 R51 R57 R58 R60-R62 R64 R66 = CRCW06033K24FKEA: RES, 3.24 k, 1%, 0.1 W, 0603; Manufacturer: Vishay-Dale; CompType: Resistor; Value: 3.24k; Res_ohm: 3240; Value_Code: 3k24; Tolerance_%: 1; Power_W: 0.1; Value2: 0.1W; VDC_V: 75; TempCo: 100 ppm/C; SizeArea_mm2: 1.28; SizeX_mm: 1.6; SizeY_mm: 0.8; EIA_Code: E96; U/M: EA; AEC Category: Q200
R47 R52 R54 = CRCW060310K2FKEA: RES, 10.2 k, 1%, 0.1 W, 0603; Manufacturer: Vishay-Dale; CompType: Resistor; Value: 10.2k; Res_ohm: 10200; Value_Code: 10k2; Tolerance_%: 1; Power_W: 0.1; Value2: 0.1W; VDC_V: 75; TempCo: 100 ppm/C; SizeArea_mm2: 1.28; SizeX_mm: 1.6; SizeY_mm: 0.8; EIA_Code: E96; U/M: EA; AEC Category: Q200
R48 R59 = CRCW06031K00FKEA: RES, 1.00 k, 1%, 0.1 W, 0603; Manufacturer: Vishay-Dale; CompType: Resistor; Value: 1.00k; Res_ohm: 1000; Value_Code: 1k00; Tolerance_%: 1; Power_W: 0.1; Value2: 0.1W; VDC_V: 75; TempCo: 100 ppm/C; SizeArea_mm2: 1.28; SizeX_mm: 1.6; SizeY_mm: 0.8; EIA_Code: E96; U/M: EA; AEC Category: Q200
R50 R53 = CRCW060310R0JNEA: RES, 10, 5%, 0.1 W, 0603; Manufacturer: Vishay-Dale; CompType: Resistor; Value: 10; Value_Code: 10R0; Tolerance_%: 5; Power_W: 0.1; Value2: 0.1W; VDC_V: 75; TempCo: 200 ppm/C; SizeArea_mm2: 1.28; SizeX_mm: 1.6; SizeY_mm: 0.8; SizeZ_mm: 1; EIA_Code: E24; U/M: EA; AEC Category: Q200
R63 R65 = ERJ-3GEY0R00V: RES, 0, 5%, 0.1 W, 0603; Manufacturer: Panasonic; CompType: Resistor; Value: 0; Value_Code: 0000; Tolerance_%: 5; Power_W: 0.1; Value2: 0.1W; VDC_V: 50; TempCo: 600 ppm/C; SizeArea_mm2: 1.28; SizeX_mm: 1.6; SizeY_mm: 0.8; SizeZ_mm: 1; EIA_Code: E24; U/M: EA; AEC Category: Q200
R67 R71 = RT0603DRE071K96L: RES, 1.96 k, 0.5%, 0.1 W, 0603; Manufacturer: Yageo America; CompType: Resistor; Value: 1.96k; Res_ohm: 1960; Value_Code: 1k96; Tolerance_%: 0.5; Power_W: 0.1; Value2: 0.1W; VDC_V: 75; TempCo: 50 ppm/C; SizeArea_mm2: 1.28; SizeX_mm: 1.6; SizeY_mm: 0.8; SizeZ_mm: 1; EIA_Code: E192; U/M: EA; AEC Category: Q200
R68 R72 = RT0603DRE072K8L: RES, 2.80 k, 0.5%, 0.1 W, 0603; Manufacturer: Yageo America; CompType: Resistor; Value: 2.80k; Res_ohm: 2800; Value_Code: 2k80; Tolerance_%: 0.5; Power_W: 0.1; Value2: 0.1W; VDC_V: 75; TempCo: 50 ppm/C; SizeArea_mm2: 1.28; SizeX_mm: 1.6; SizeY_mm: 0.8; SizeZ_mm: 1; EIA_Code: E192; U/M: EA; AEC Category: Q200
R69 = RT0603BRD0712K7L: RES, 12.7 k, 0.1%, 0.1 W, 0603; Manufacturer: Yageo America; CompType: Resistor; Value: 12.7k; Res_ohm: 12700; Value_Code: 12k7; Tolerance_%: 0.1; Value2: 0.1W; VDC_V: 75; TempCo: 25 ppm/C; SizeArea_mm2: 1.28; SizeX_mm: 1.6; SizeY_mm: 0.8; SizeZ_mm: 1; EIA_Code: E192; U/M: EA; AEC Category: Q200
R70 = CRCW060310K0FKEA: RES, 10.0 k, 1%, 0.1 W, 0603; Manufacturer: Vishay-Dale; CompType: Resistor; Value: 10.0k; Res_ohm: 10000; Value_Code: 10k0; Tolerance_%: 1; Power_W: 0.1; Value2: 0.1W; VDC_V: 75; TempCo: 100 ppm/C; SizeArea_mm2: 1.28; SizeX_mm: 1.6; SizeY_mm: 0.8; EIA_Code: E96; U/M: EA; AEC Category: Q200
U5 = LP87524FRNFRQ1: Four-Phase Buck Converter Up to 10-A Total Current with Integrated Switches, RNF0026C (VQFN-HR-26); Manufacturer: Texas Instruments; SymbolCreator: Altium; SizeArea_mm2: 18; SizeAreaWB_mm2: 27.5; SizeX_mm: 4; SizeY_mm: 4.5; SizeZ_mm: 0.9; CompType: IC; U/M: EA
U6 = TPS3780ADRYR: Low Power, Dual Voltage Detector in Small uSON package, DRY0006A (USON-6); Alternate PartNumber: TPS3780ADRYT; Manufacturer: Texas Instruments; SymbolCreator: x0208326; SizeArea_mm2: 1.45; SizeAreaWB_mm2: 4.9; SizeX_mm: 1; SizeZ_mm: 0.6; CompType: IC; U/M: EA
U7 = TPS7A8801RTJR: Dual, 1-A, Low Noise (3.8-μVRMS), LDO Voltage Regulator, RTJ0020D (WQFN-20); Alternate PartNumber: TPS7A8801RTJT; Manufacturer: Texas Instruments; SymbolCreator: Altium; SizeArea_mm2: 16; SizeAreaWB_mm2: 25; SizeX_mm: 4; SizeZ_mm: 0.8; CompType: IC; U/M: EA
U8 = TPS7A8101DRBR: Low-Noise, High-Bandwidth PSRR, Low-Dropout 1-A Linear Regulator, DRB0008A (VSON-8); Alternate PartNumber: TPS7A8101DRBT; Manufacturer: Texas Instruments; SymbolCreator: Altium; SizeArea_mm2: 9; SizeAreaWB_mm2: 16; SizeX_mm: 3; SizeZ_mm: 1; CompType: IC; U/M: EA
